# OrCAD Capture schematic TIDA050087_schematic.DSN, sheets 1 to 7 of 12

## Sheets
1 P07: i.MX93 MISC: size C
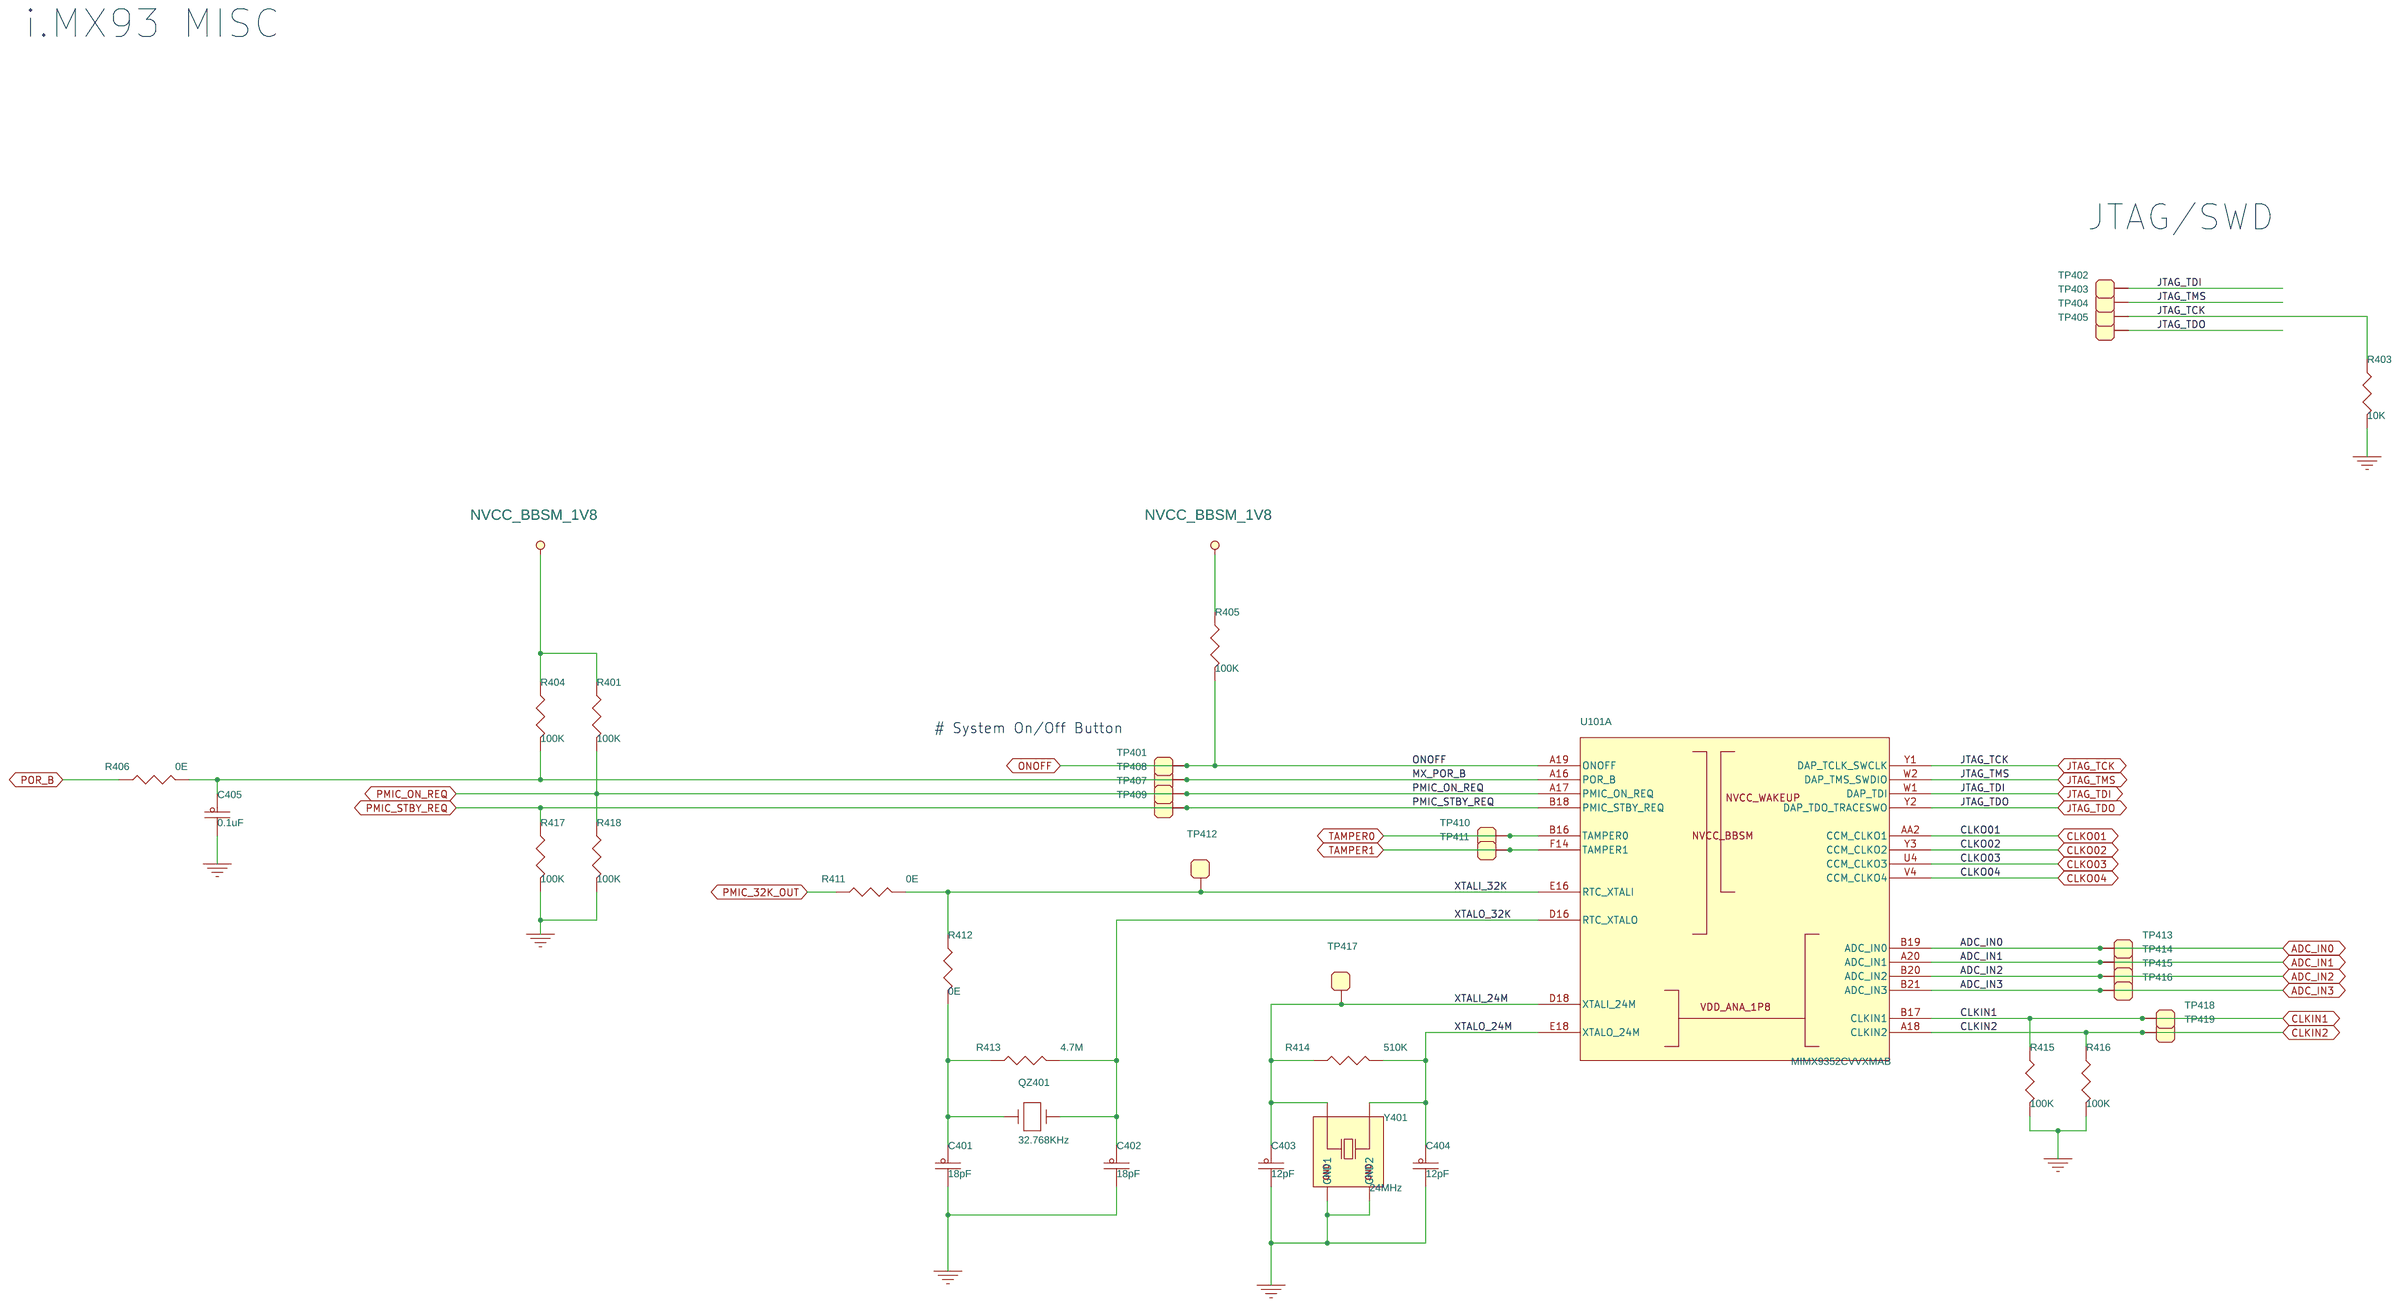
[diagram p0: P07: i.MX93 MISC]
2 P05: LPDDR4: size C
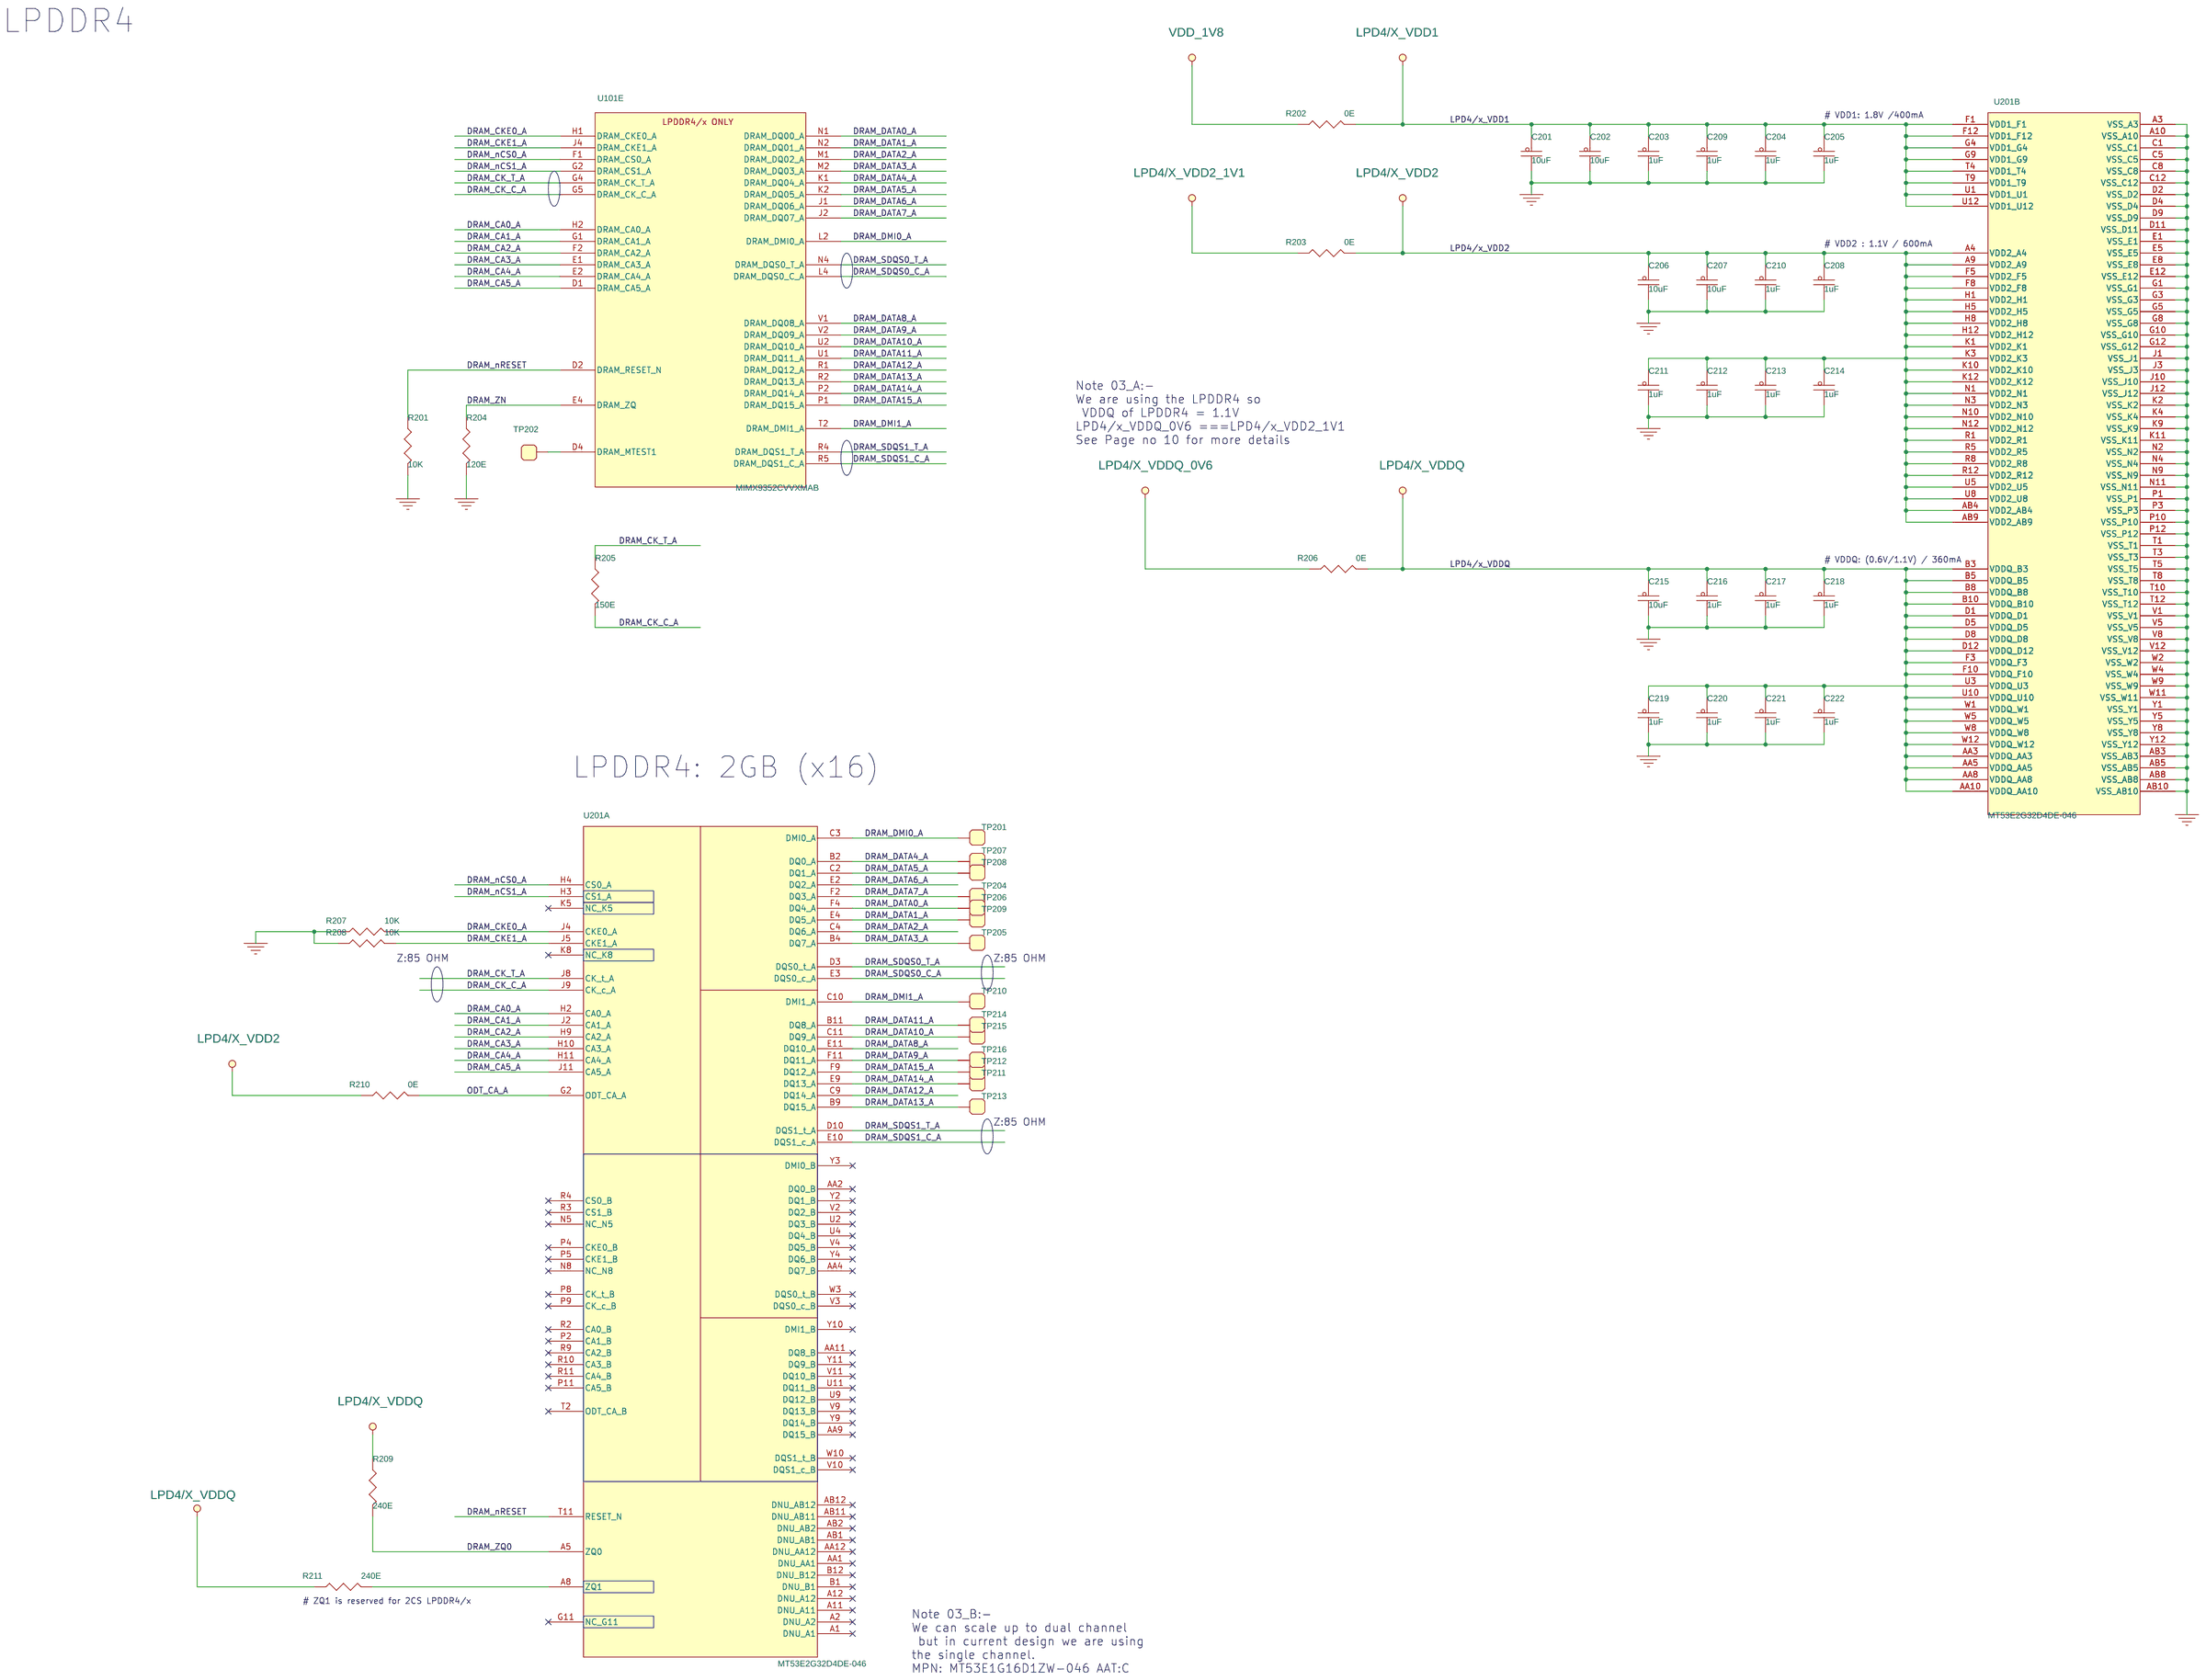
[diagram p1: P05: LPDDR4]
3 P08: eMMC: size C
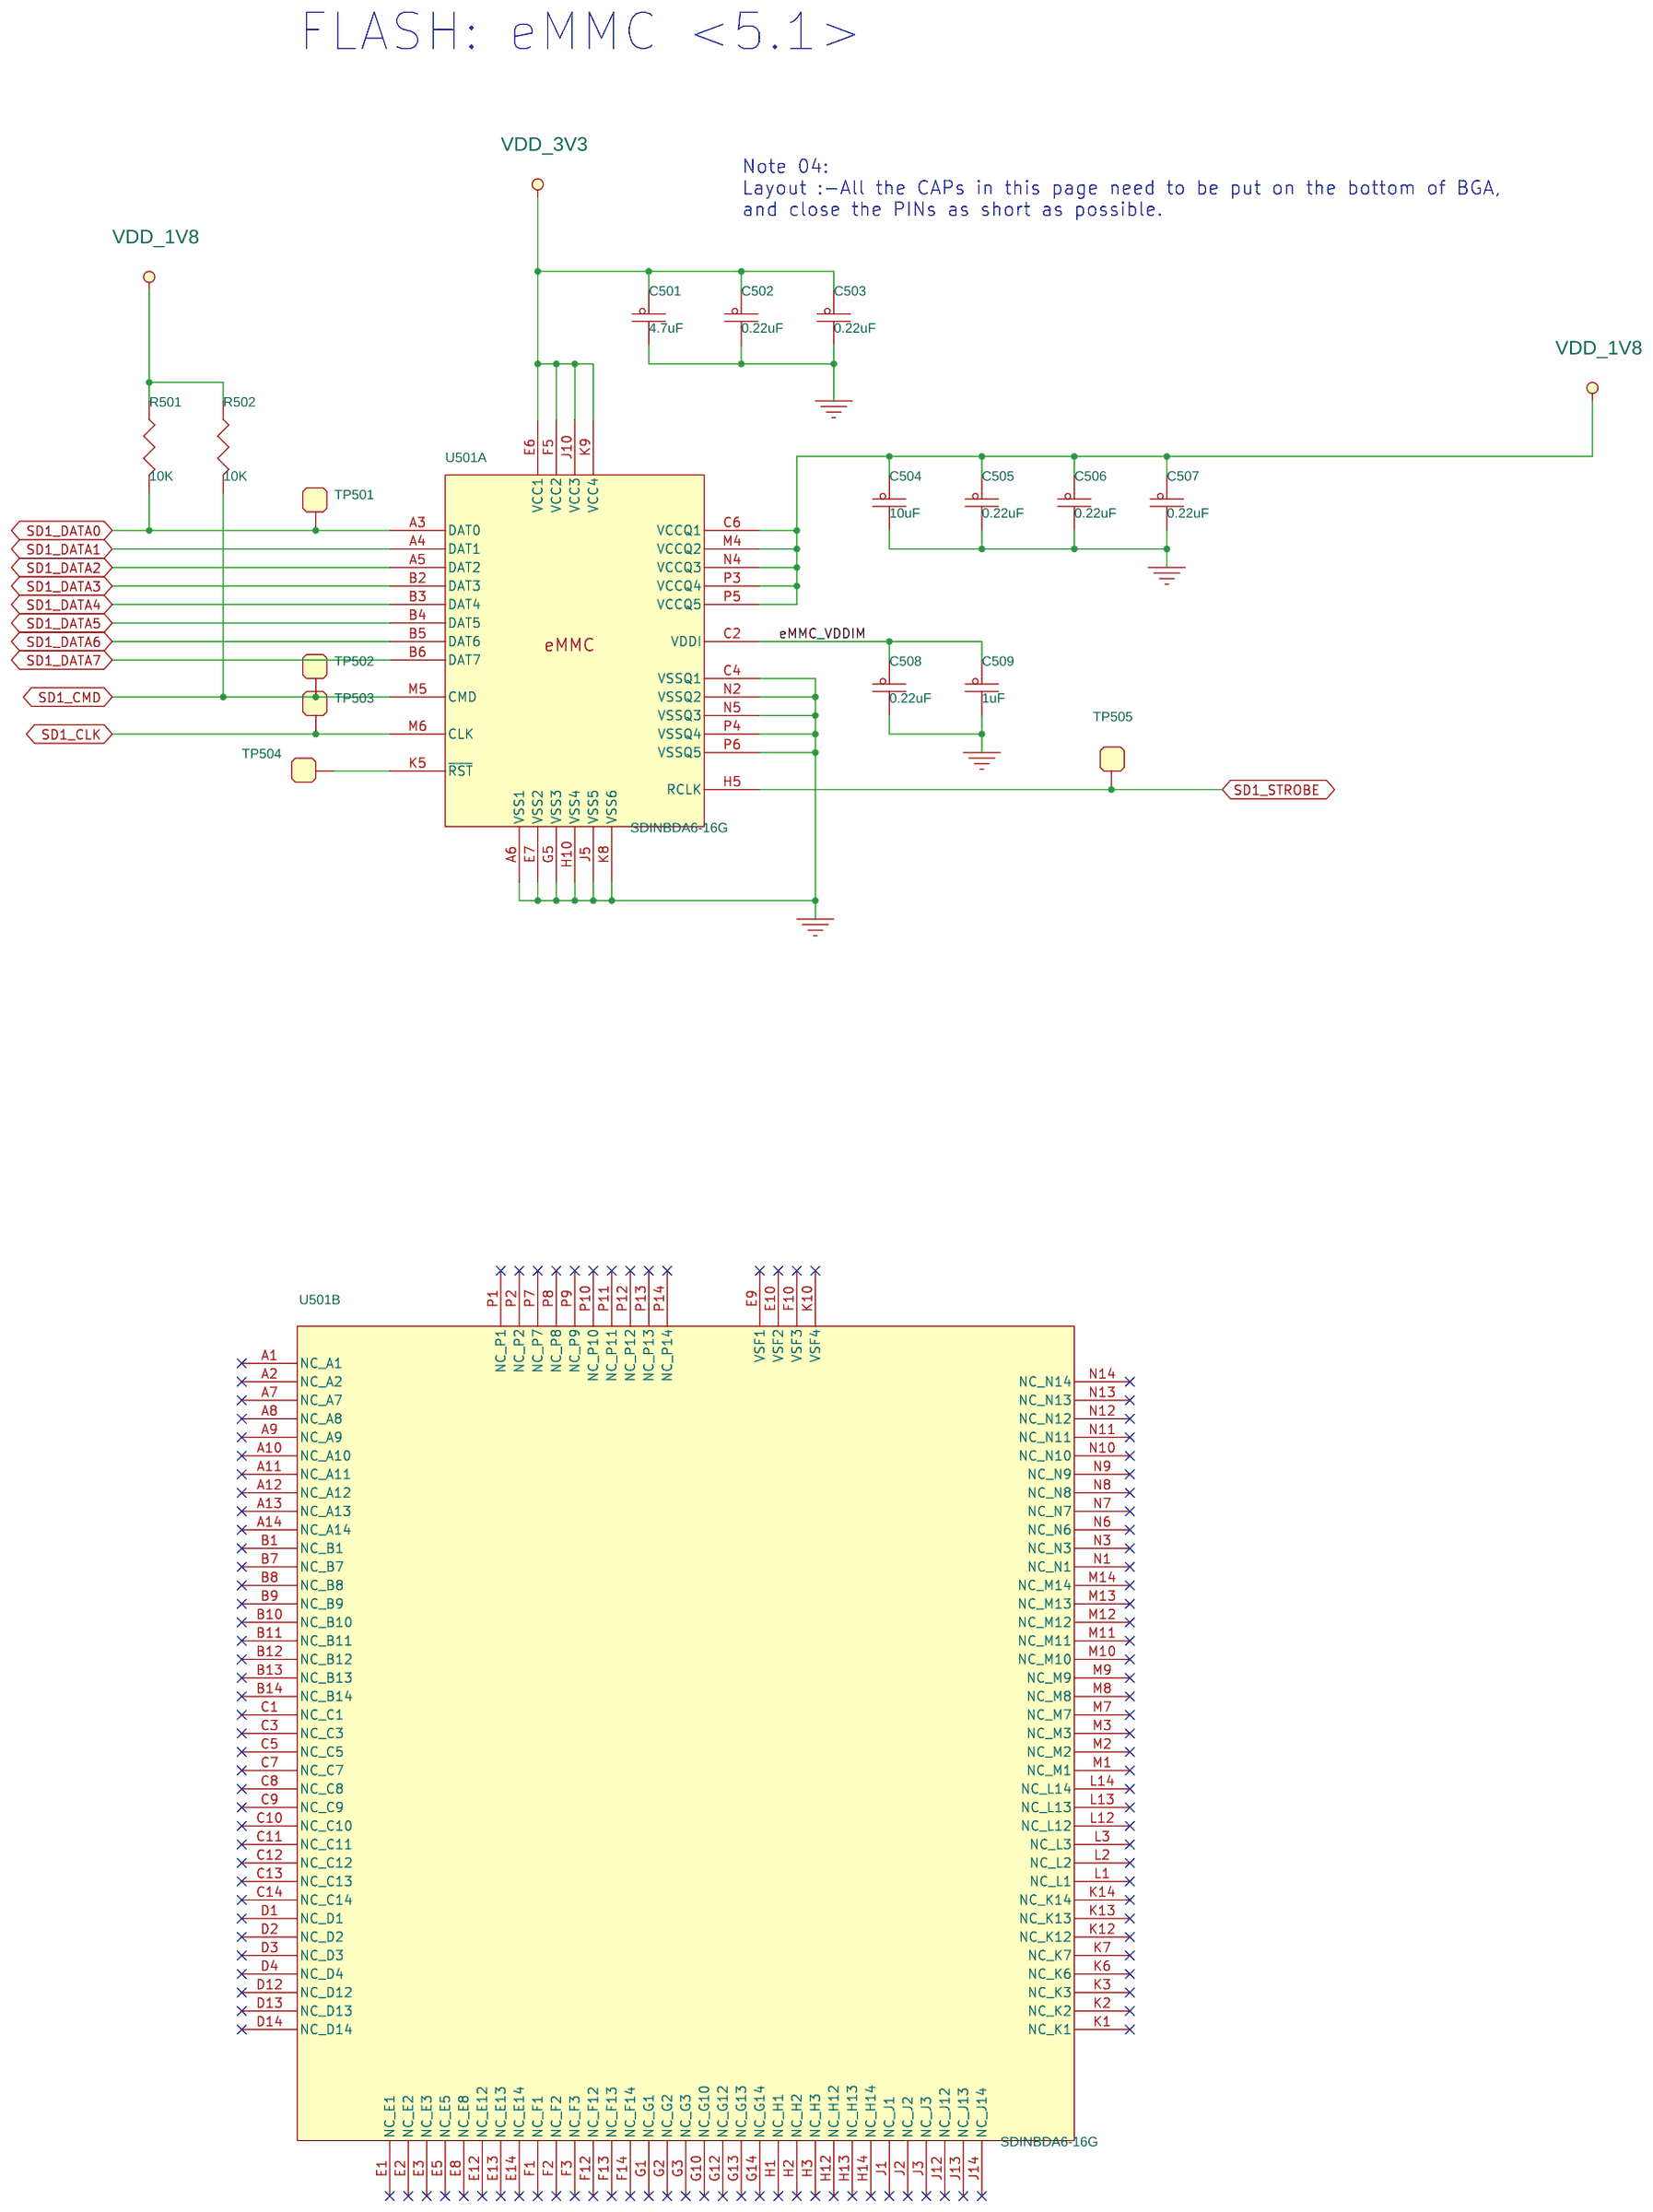
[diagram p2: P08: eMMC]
4 P01: COVER PAGE
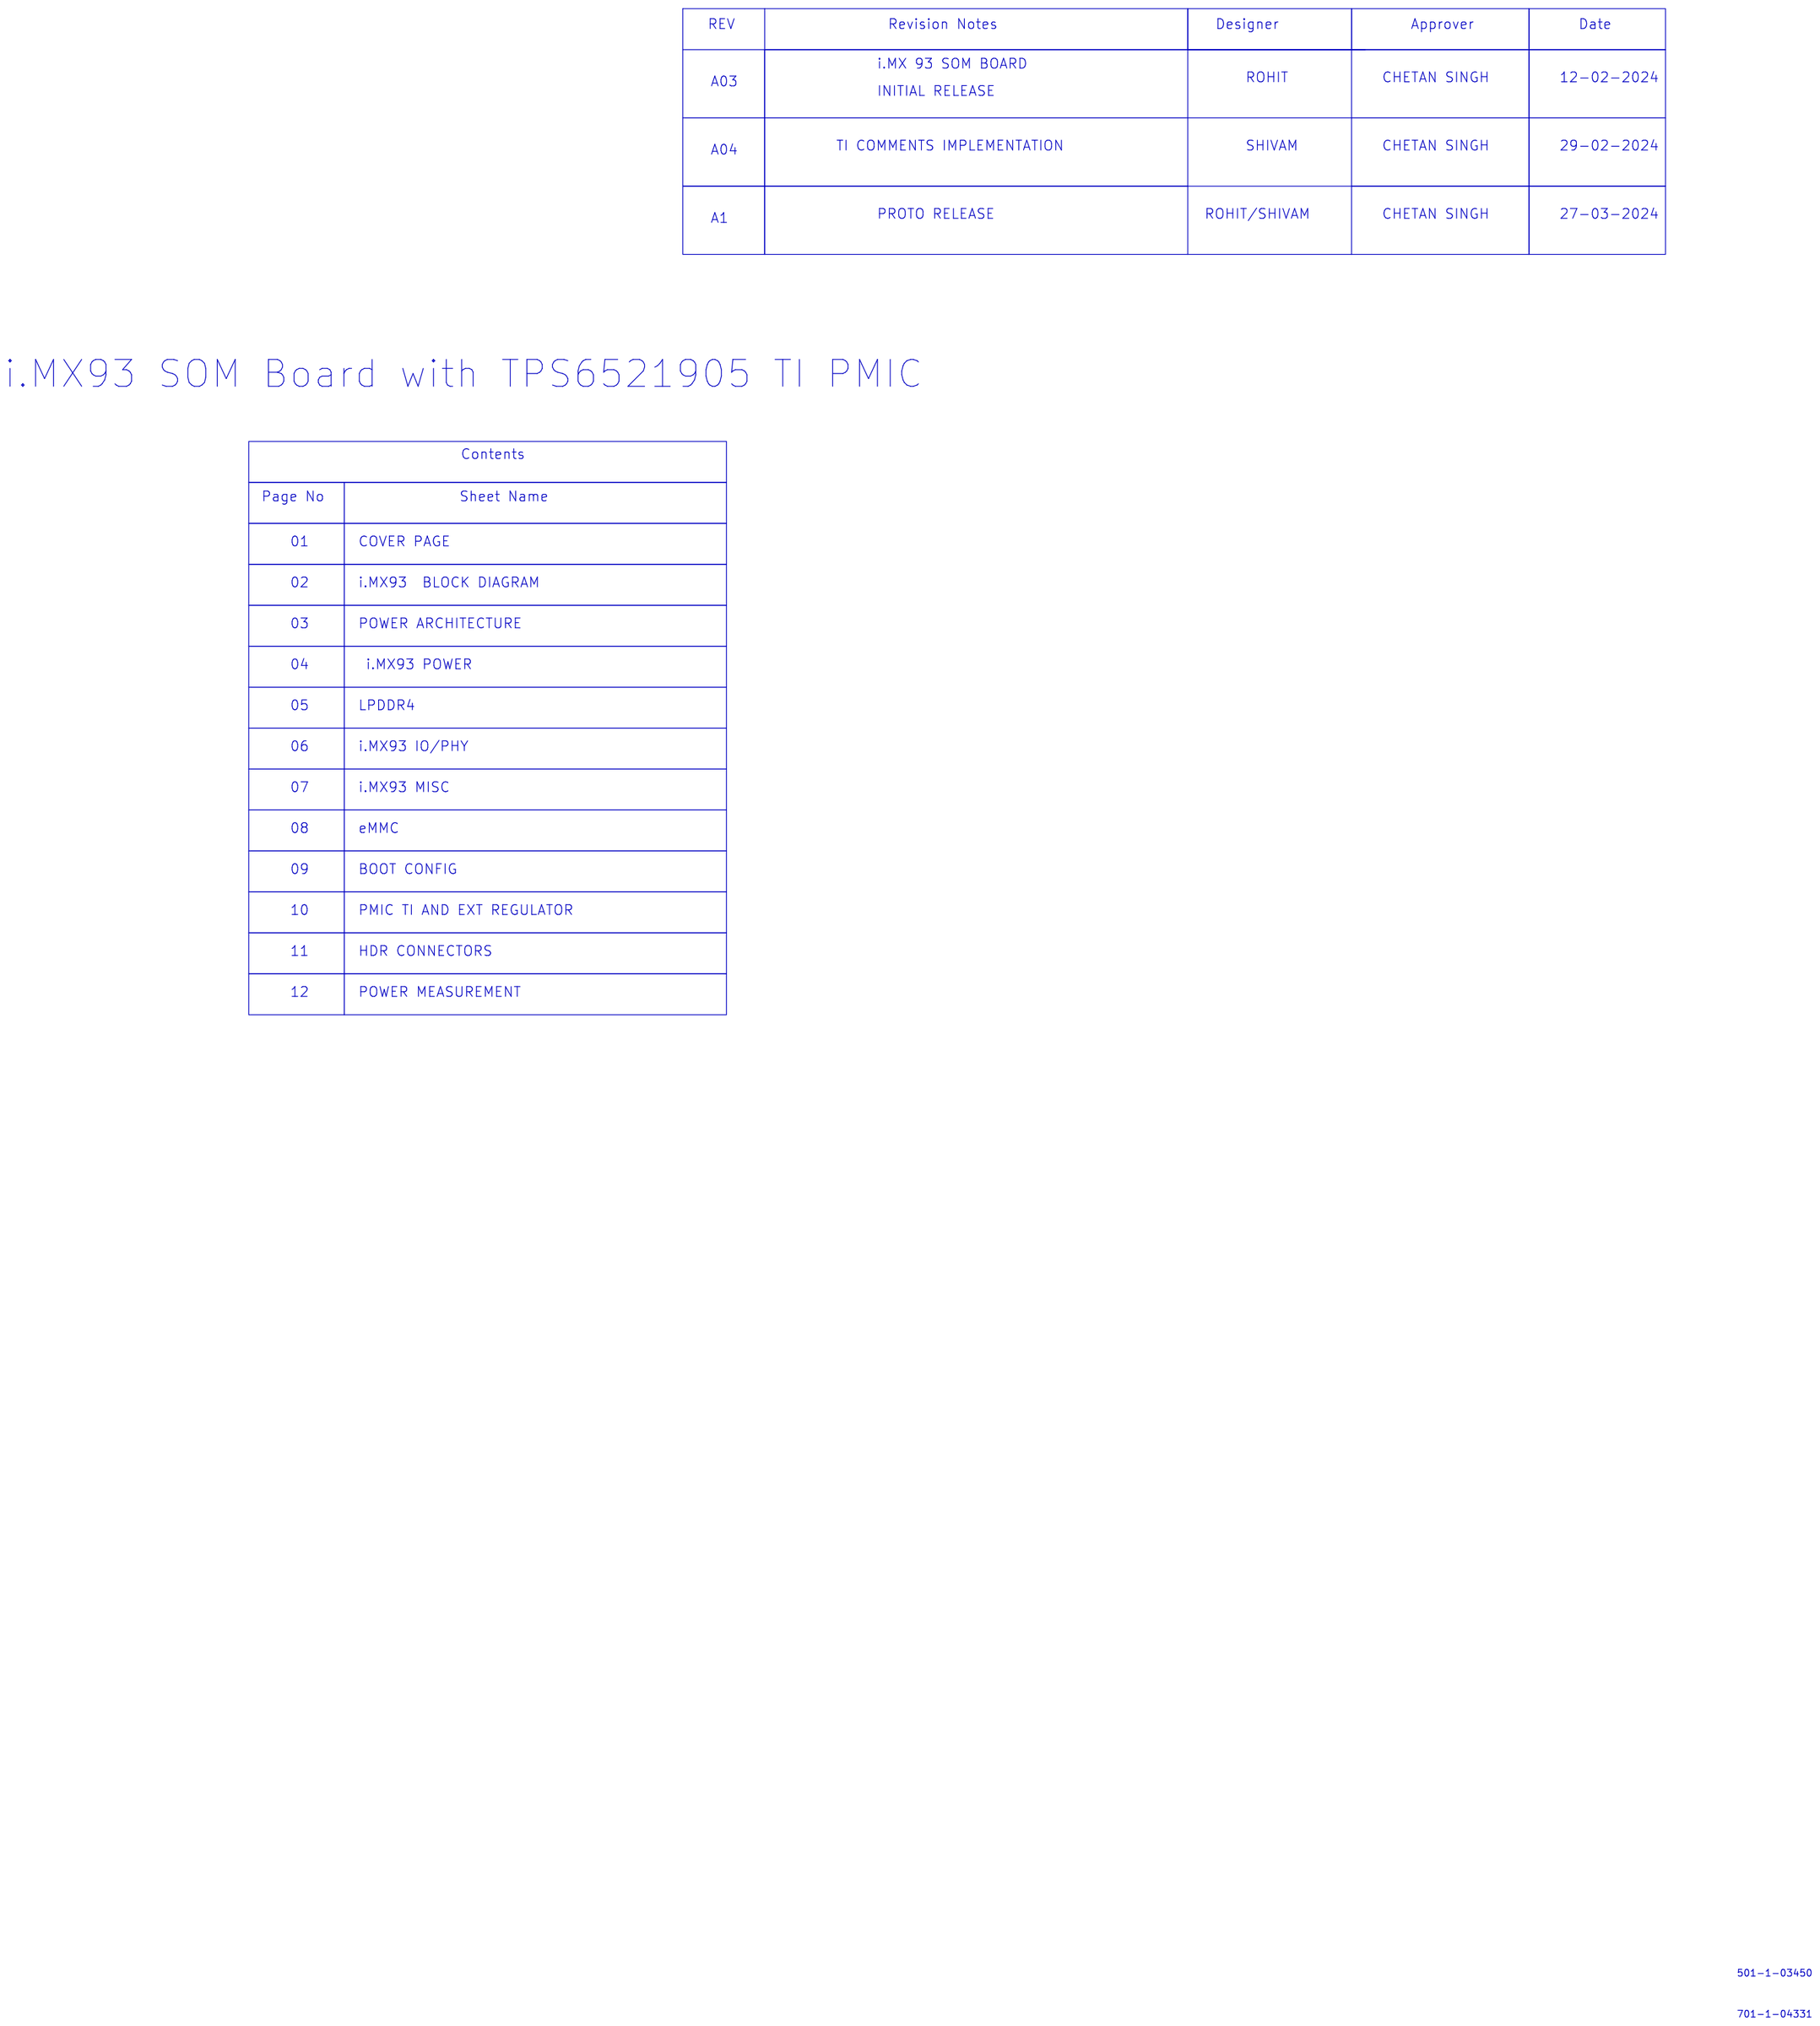
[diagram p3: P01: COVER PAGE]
5 P11: HDR CONNECTORS: size C
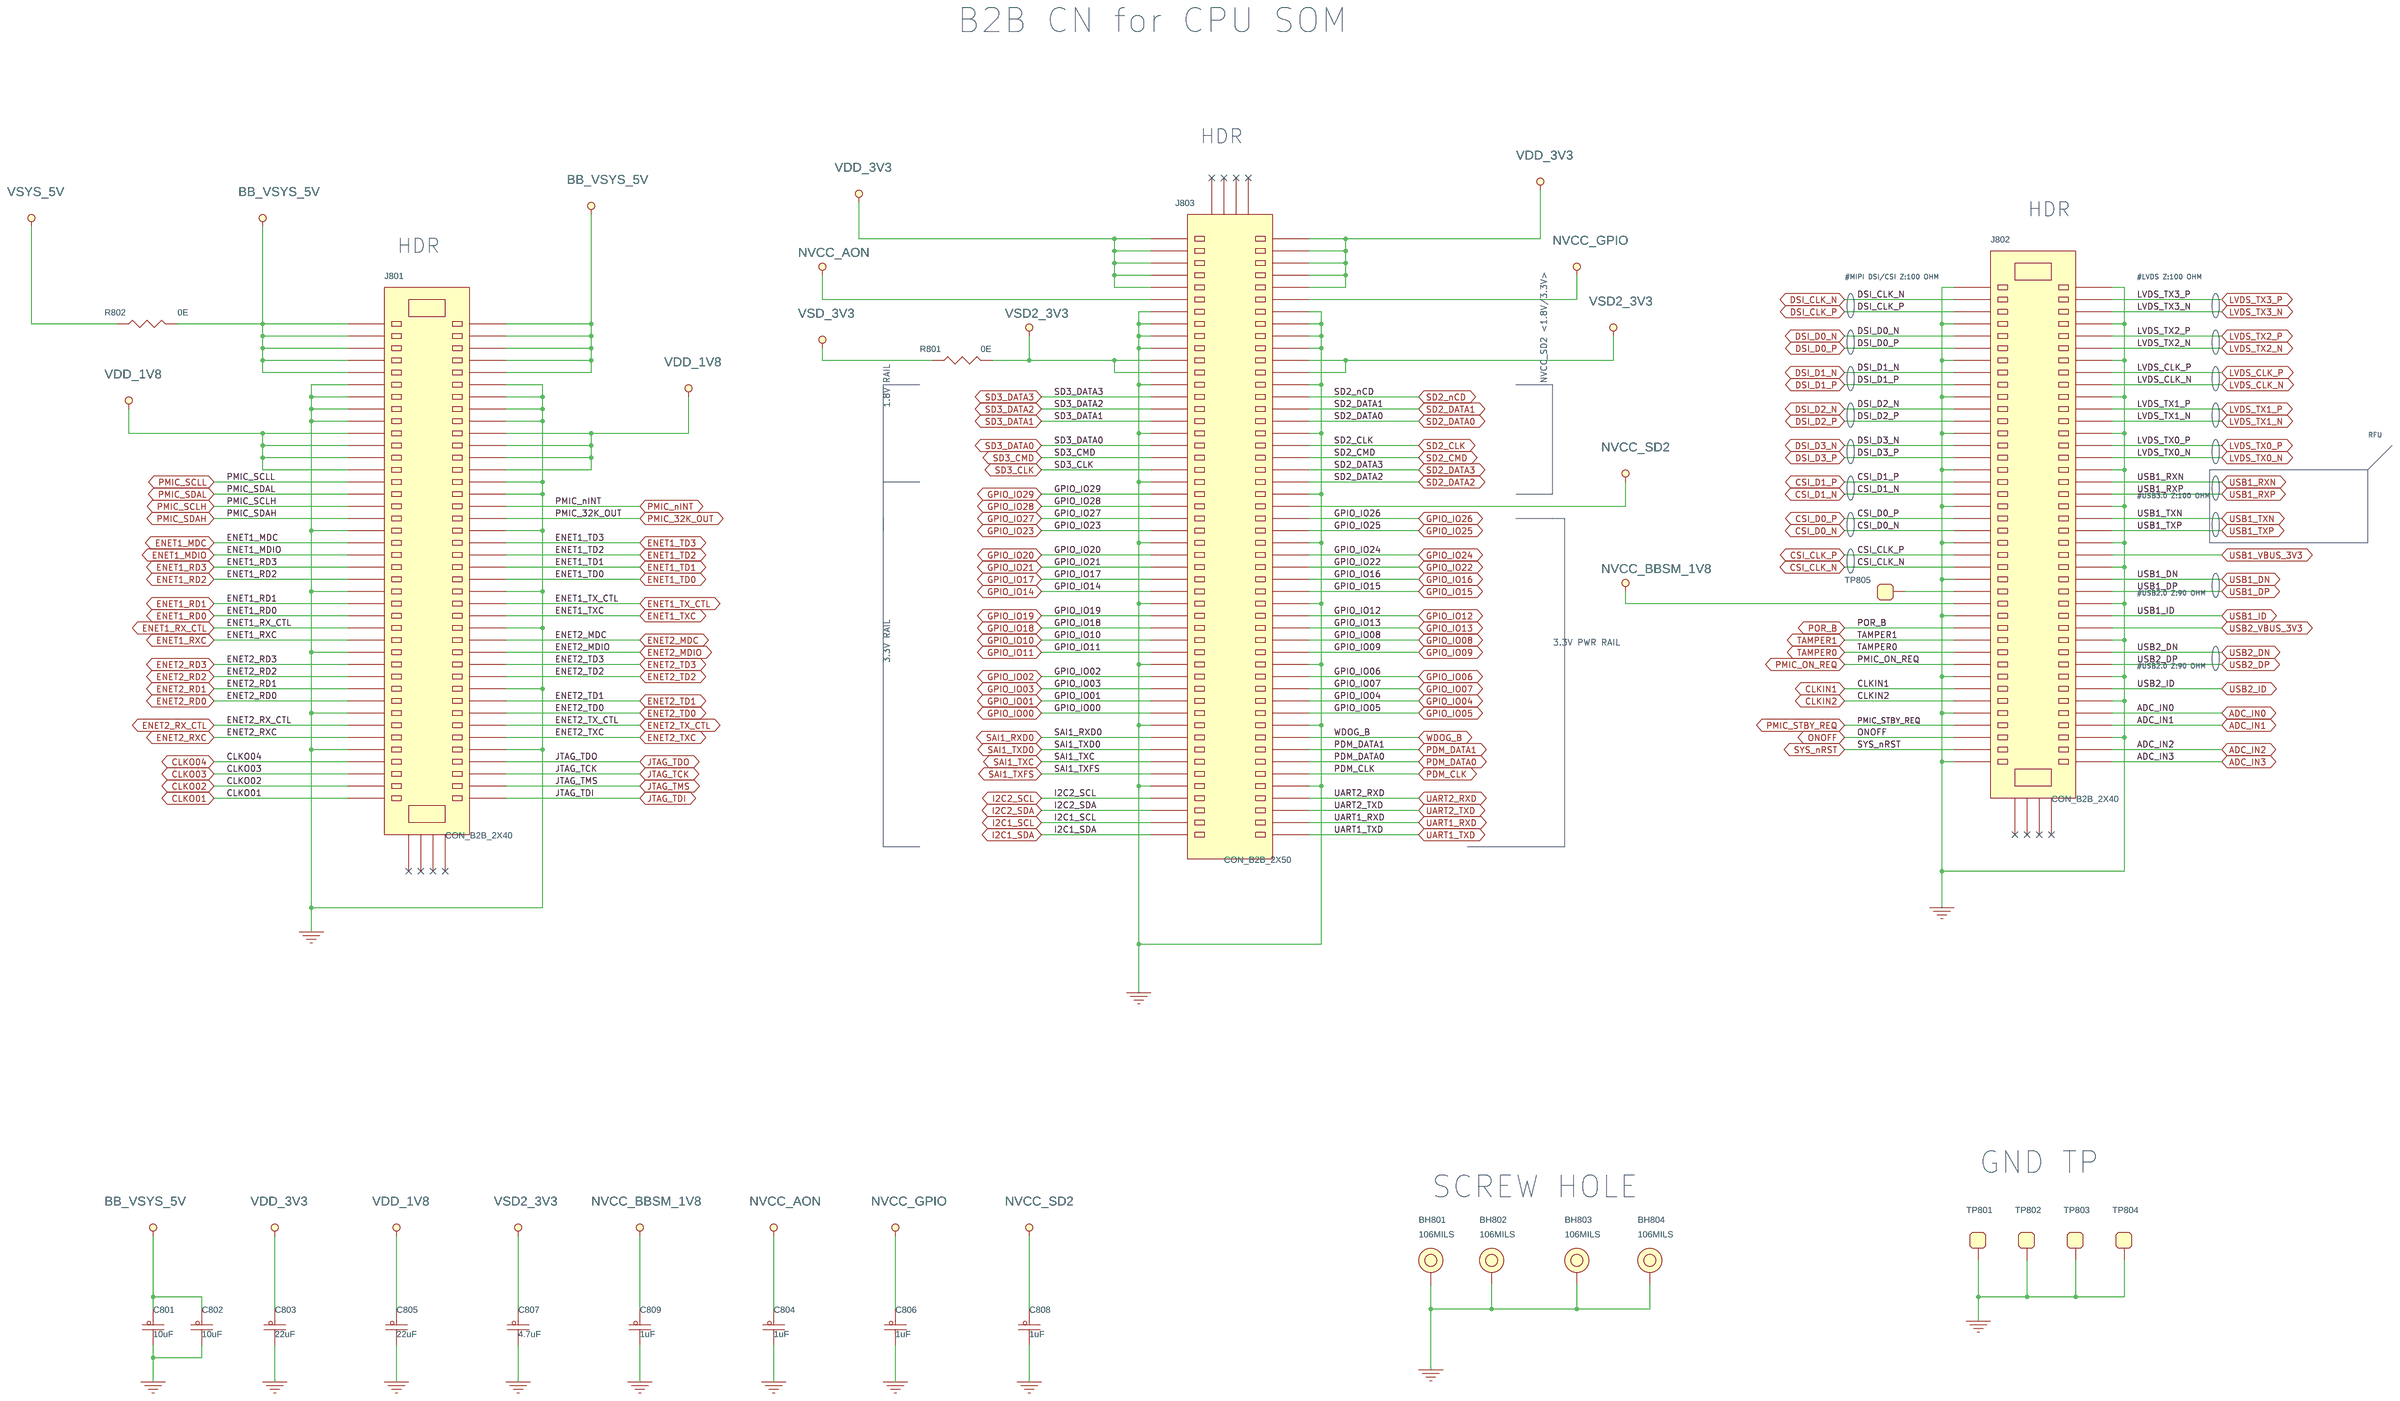
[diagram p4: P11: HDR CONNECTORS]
6 P04: i.MX93 POWER: size C
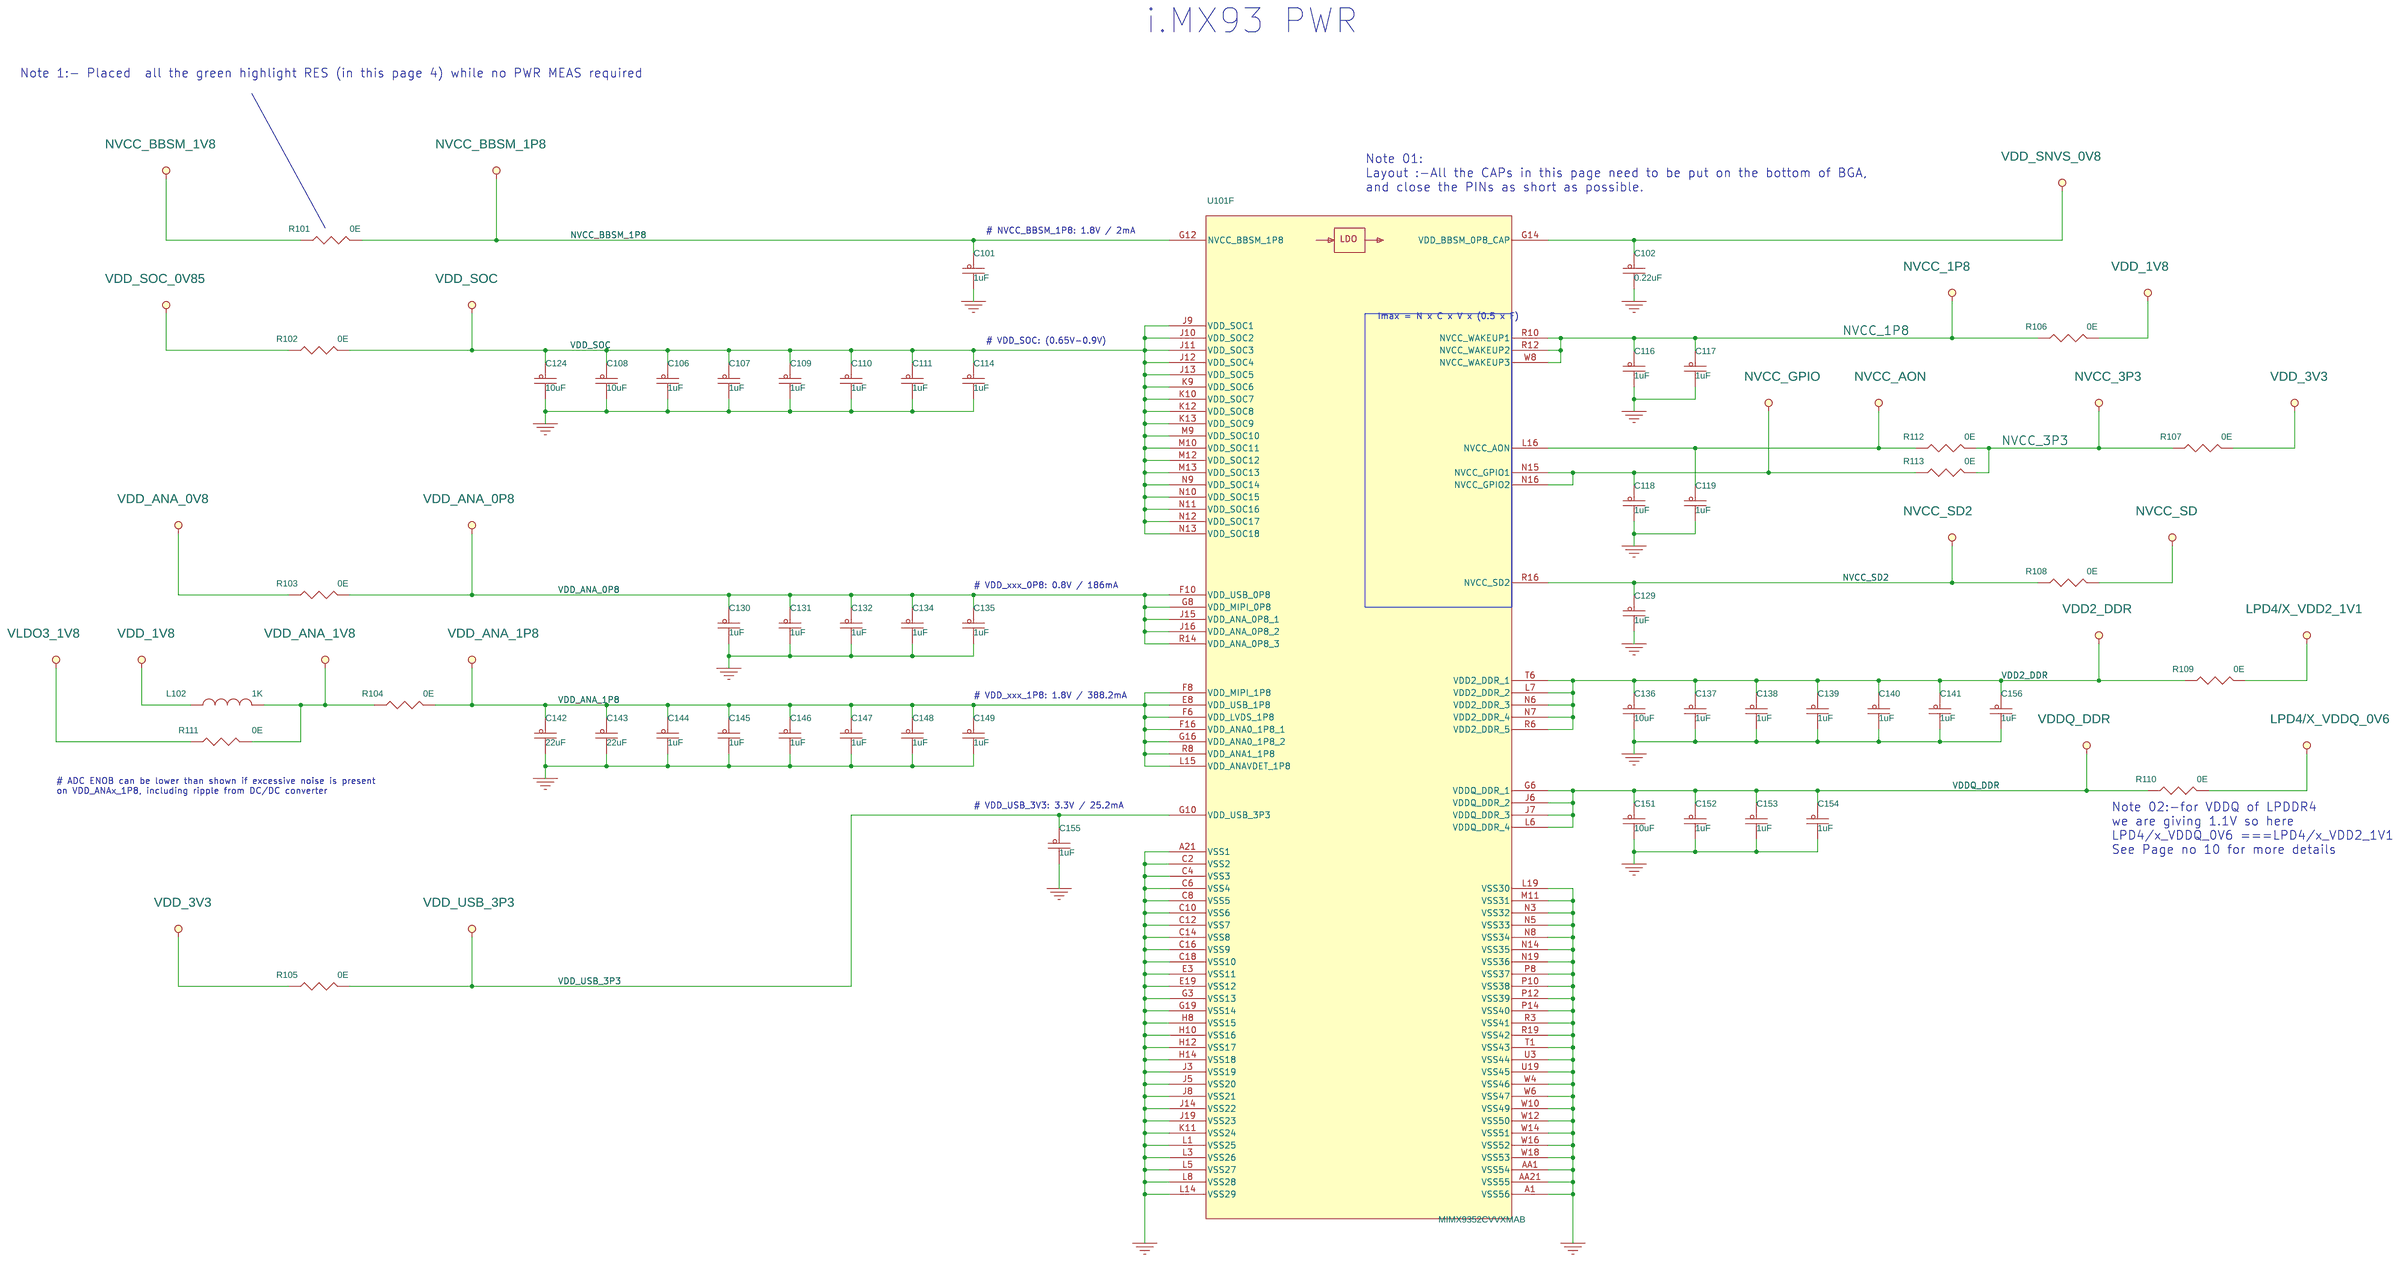
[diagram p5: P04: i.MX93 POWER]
7 P09: BOOT CONFIG: size C
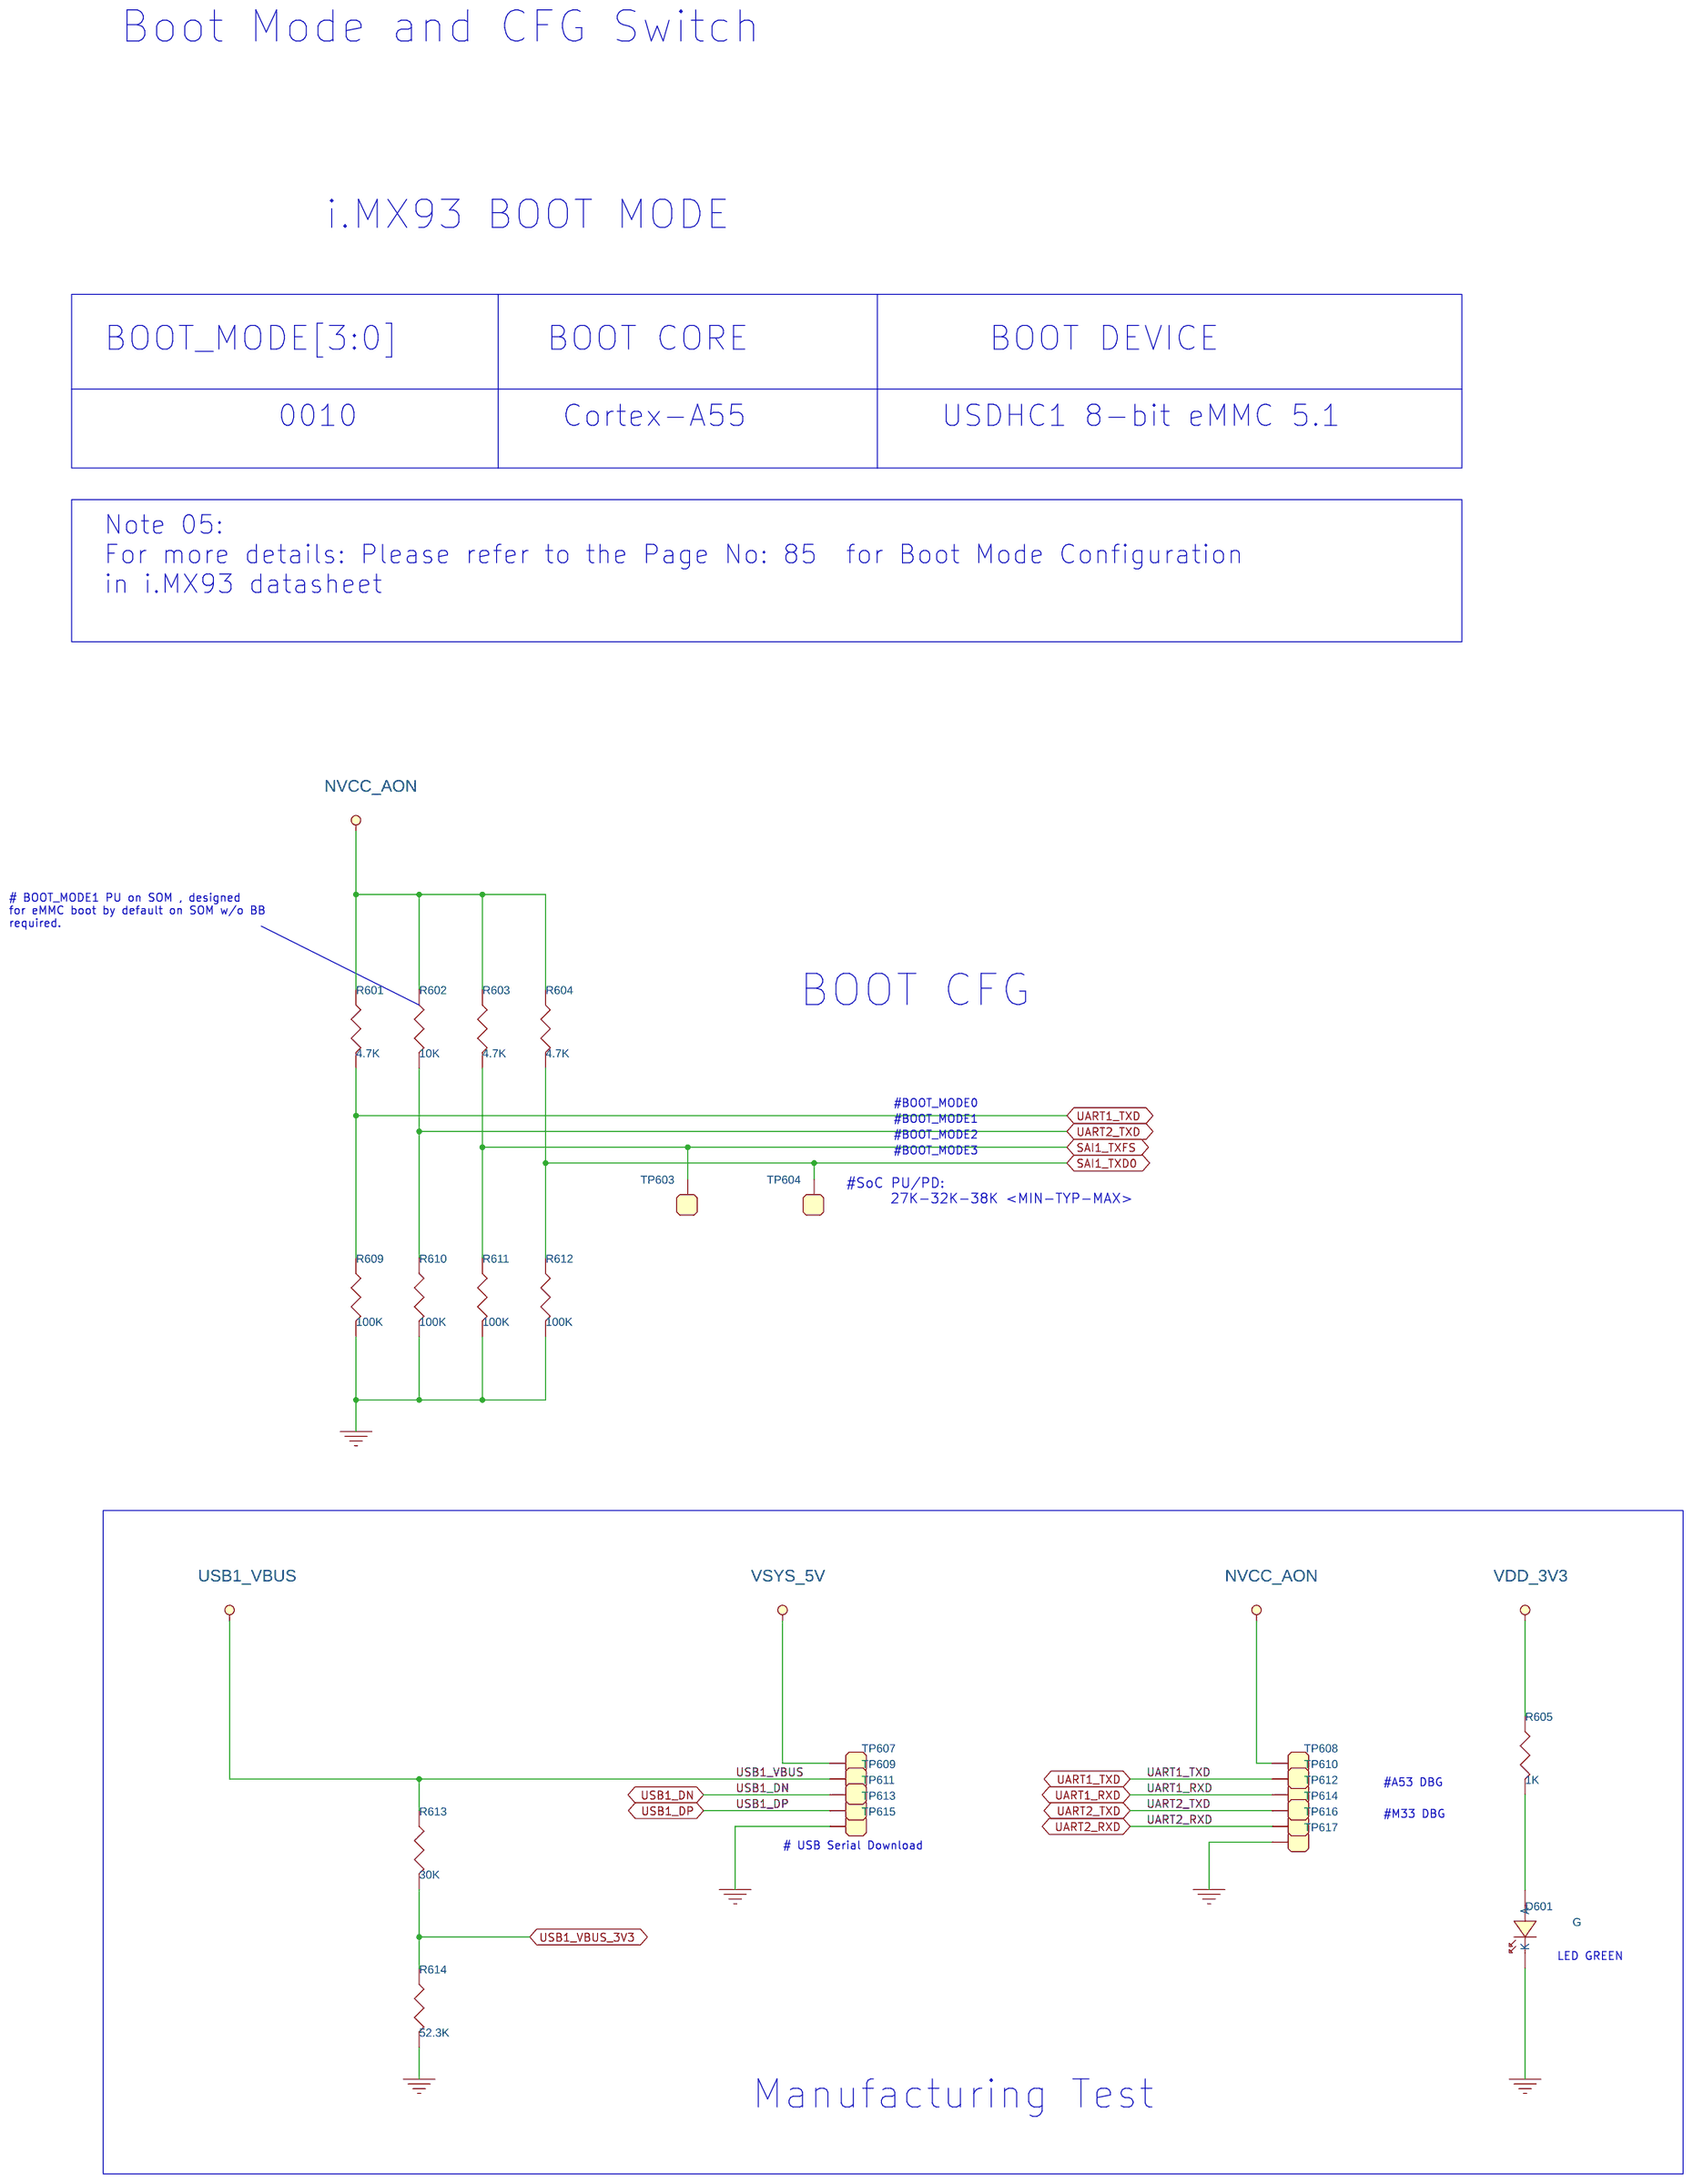
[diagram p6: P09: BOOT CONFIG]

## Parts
sheet P04: i.MX93 POWER
C101  1uF  [0201]
C102  0.22uF  [0201]
C106  1uF  [0201]
C107  1uF  [0201]
C108  10uF  [0402]
C109  1uF  [0201]
C110  1uF  [0201]
C111  1uF  [0201]
C114  1uF  [0201]
C116  1uF  [0201]
C117  1uF  [0201]
C118  1uF  [0201]
C119  1uF  [0201]
C124  10uF  [0402]
C129  1uF  [0201]
C130  1uF  [0201]
C131  1uF  [0201]
C132  1uF  [0201]
C134  1uF  [0201]
C135  1uF  [0201]
C136  10uF  [0402]
C137  1uF  [0201]
C138  1uF  [0201]
C139  1uF  [0201]
C140  1uF  [0201]
C141  1uF  [0201]
C142  22uF  [0603]
C143  22uF  [0603]
C144  1uF  [0201]
C145  1uF  [0201]
C146  1uF  [0201]
C147  1uF  [0201]
C148  1uF  [0201]
C149  1uF  [0201]
C151  10uF  [0402]
C152  1uF  [0201]
C153  1uF  [0201]
C154  1uF  [0201]
C155  1uF  [0201]
C156  1uF  [0201]
L102  1K  [FBEAD-0603_A_A1]
R101  0E  [0402]
R102  0E  [RC0805]
R103  0E  [RC0603]
R104  0E  [RC0603]
R105  0E  [0402]
R106  0E  [0402]
R107  0E  [0402]
R108  0E  [0402]
R109  0E  [RC0603]
R110  0E  [RC0603]
R111  0E  [RC0603]
R112  0E  [0402]
R113  0E  [0402]
sheet P05: LPDDR4
C201  10uF  [0402]
C202  10uF  [0402]
C203  1uF  [0201]
C204  1uF  [0201]
C205  1uF  [0201]
C206  10uF  [0402]
C207  10uF  [0402]
C208  1uF  [0201]
C209  1uF  [0201]
C210  1uF  [0201]
C211  1uF  [0201]
C212  1uF  [0201]
C213  1uF  [0201]
C214  1uF  [0201]
C215  10uF  [0402]
C216  1uF  [0201]
C217  1uF  [0201]
C218  1uF  [0201]
C219  1uF  [0201]
C220  1uF  [0201]
C221  1uF  [0201]
C222  1uF  [0201]
R201  10K  [0402]
R202  0E  [RC0603]
R203  0E  [RC0603]
R204  120E  [0402]
R205  150E  [0402]
R206  0E  [RC0603]
R207  10K  [0402]
R208  10K  [0402]
R209  240E  [0201]
R210  0E  [0402]
R211  240E  [0201]
TP201  SMD  [TP20_SMD]
TP202  SMD  [TP20_SMD]
TP204  SMD  [TP20_SMD]
TP205  SMD  [TP20_SMD]
TP206  SMD  [TP20_SMD]
TP207  SMD  [TP20_SMD]
TP208  SMD  [TP20_SMD]
TP209  SMD  [TP20_SMD]
TP210  SMD  [TP20_SMD]
TP211  SMD  [TP20_SMD]
TP212  SMD  [TP20_SMD]
TP213  SMD  [TP20_SMD]
TP214  SMD  [TP20_SMD]
TP215  SMD  [TP20_SMD]
TP216  SMD  [TP20_SMD]
U201  MT53E2G32D4DE-046  [BGA200_0P65_10X14P5_F_A1]  (sections A,B)
sheet P06: i.MX93 IO/PHY
U101  MIMX9352CVVXMAB  [BGA306_0P5_11X11_CST_A1]  (sections A,B,C,D,E,F)
sheet P07: i.MX93 MISC
C401  18pF  [0201]
C402  18pF  [0201]
C403  12pF  [0201]
C404  12pF  [0201]
C405  0.1uF  [0402]
QZ401  32.768KHz  [XTAL2_2P5_3P2X1P5]
R401  100K  [0402]
R403  10K  [0402]
R404  100K  [0402]
R405  100K  [0402]
R406  0E  [0201]
R411  0E  [0201]
R412  0E  [0201]
R413  4.7M  [0402]
R414  510K  [0402]
R415  100K  [0402]
R416  100K  [0402]
R417  100K  [0402]
R418  100K  [0402]
TP401  SMD  [TP20_SMD]
TP402  SMD  [TP20_SMD]
TP403  SMD  [TP20_SMD]
TP404  SMD  [TP20_SMD]
TP405  SMD  [TP20_SMD]
TP407  SMD  [TP20_SMD]
TP408  SMD  [TP20_SMD]
TP409  SMD  [TP20_SMD]
TP410  SMD  [TP20_SMD]
TP411  SMD  [TP20_SMD]
TP412  SMD  [TP20_SMD]
TP413  SMD  [TP20_SMD]
TP414  SMD  [TP20_SMD]
TP415  SMD  [TP20_SMD]
TP416  SMD  [TP20_SMD]
TP417  SMD  [TP20_SMD]
TP418  SMD  [TP20_SMD]
TP419  SMD  [TP20_SMD]
Y401  24MHz  [XTAL4_1P6_3P2X2P5_A_A1]
sheet P08: eMMC
C501  4.7uF  [0402]
C502  0.22uF  [0201]
C503  0.22uF  [0201]
C504  10uF  [0402]
C505  0.22uF  [0201]
C506  0.22uF  [0201]
C507  0.22uF  [0201]
C508  0.22uF  [0201]
C509  1uF  [0201]
R501  10K  [0402]
R502  10K  [0402]
TP501  SMD  [TP20_SMD]
TP502  SMD  [TP20_SMD]
TP503  SMD  [TP20_SMD]
TP504  SMD  [TP20_SMD]
TP505  SMD  [TP20_SMD]
U501  SDINBDA6-16G  [BGA153_0P5_11P5X13_C_A2]  (sections A,B)
sheet P09: BOOT CONFIG
D601  G  [LED-0603_L_A1]
R601  4.7K  [0402]
R602  10K  [0402]
R603  4.7K  [0402]
R604  4.7K  [0402]
R605  1K  [0402]
R609  100K  [0402]
R610  100K  [0402]
R611  100K  [0402]
R612  100K  [0402]
R613  30K  [0402]
R614  52.3K  [0201]
TP603  SMD  [TP35_SMD]
TP604  SMD  [TP35_SMD]
TP607  SMD  [TP35_SMD]
TP608  SMD  [TP35_SMD]
TP609  SMD  [TP35_SMD]
TP610  SMD  [TP35_SMD]
TP611  SMD  [TP35_SMD]
TP612  SMD  [TP35_SMD]
TP613  SMD  [TP35_SMD]
TP614  SMD  [TP35_SMD]
TP615  SMD  [TP35_SMD]
TP616  SMD  [TP35_SMD]
TP617  SMD  [TP35_SMD]
sheet P11: HDR CONNECTORS
BH801  106MILS  [MH_CIR173D106T_CUST]
BH802  106MILS  [MH_CIR173D106T_CUST]
BH803  106MILS  [MH_CIR173D106T_CUST]
BH804  106MILS  [MH_CIR173D106T_CUST]
C801  10uF  [0603]
C802  10uF  [0603]
C803  22uF  [0603]
C804  1uF  [0201]
C805  22uF  [0603]
C806  1uF  [0201]
C807  4.7uF  [0402]
C808  1uF  [0201]
C809  1uF  [0201]
J801  CON_B2B_2X40  [CON_B2B_2X40M_0P4_SM_ST_D_A1]
J802  CON_B2B_2X40  [CON_B2B_2X40M_0P4_SM_ST_D_A1]
J803  CON_B2B_2X50  [CON_B2B_2X50M_0P4_SM_ST_A_A2]
R801  0E  [RC0603]
R802  0E  [RC0805]
TP801  SMD  [TP50_SMD]
TP802  SMD  [TP50_SMD]
TP803  SMD  [TP50_SMD]
TP804  SMD  [TP50_SMD]
TP805  SMD  [TP35_SMD]

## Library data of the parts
C101 C106 C107 C109-C111 C114 C116-C119 C129-C132 C134 C135 C137-C141 C144-C149 C152-C156 C203-C205 C208-C214 C216-C222 C509 C804 C806 C808 C809 = CAP_NP: Cap, Cer-X5R, 1uF, 10V, 10%, 0201; EN: 102-1-02132; KEY Number: 102-1-02132@1; Mfg: SAMSUNG ELECTRO-MECHANICS AMERICA, INC; Mfg Part No: CL03A105KP3NSNC; Part Status: 3SILVER; RoHS Status: ROHS; Temperature: -55°C to +85°C
C102 C502 C503 C505-C508 = CAP_NP: Cap, Cer-X5R, 0.22uF, 10V, 20%, 0201; EN: 102-1-02582; KEY Number: 102-1-02582@1; Mfg: TAIYO YUDEN; Mfg Part No: LMK063BJ224MP-F; Part Status: 3SILVER; Temperature: -55°C to +85°C
C108 C124 C136 C151 C201 C202 C206 C207 C215 C504 = CAP_NP: Cap, Cer-X5R, 10uF, 6.3V, 20%, 0402; EN: 102-1-05247; KEY Number: 102-1-05247@1; Mfg: SAMSUNG ELECTRO-MECHANICS AMERICA, INC; Mfg Part No: CL05A106MQ5NUNC; Part Status: 3SILVER
C142 C143 C803 C805 = CAP_NP: Cap, Cer-X5R, 22uF, 10V, 20%, 0603; EN: 102-1-01791; KEY Number: 102-1-01791@1; Mfg: TDK CORPORATION; Mfg Part No: C1608X5R1A226M080AC; Part Status: 3SILVER; RoHS Status: RoHS; Temperature: -55°C to +85°C
L102 = FER_BEAD: F-Bead, 1K, 1.2A, SMD0603; EN: 104-1-00485; KEY Number: 104-1-00485@1; Mfg: MURATA MANUFACTURING CO,LTD; Mfg Part No: BLM18SP102SN1D; Part Status: 3SILVER; RoHS Status: RoHS; Temperature: -55°C to +125°C
R101 R105-R108 R112 R113 R210 = RES: Res, Chip, 0E, 1/16W, 5%, 0402; EN: 101-1-08134; KEY Number: 101-1-08134@1; Mfg: YAGEO CORPORATION; Mfg Part No: RC0402JR-070RL; Part Status: 3SILVER; RoHS Status: RoHS; Temperature: -55°C to +155°C
R102 R802 = RES: Res, Chip, 0E, 1/8W, 5A, 0805; EN: 101-1-03831; KEY Number: 101-1-03831@1; Mfg: YAGEO CORPORATION; Mfg Part No: RC0805JR-070RL; Part Status: 3SILVER; Temperature: -55°C to +155°C
R103 R104 R109-R111 R202 R203 R206 R801 = RES: Res, Chip, 0E, 1/10W, 1A, 0603; EN: 101-1-08684; KEY Number: 101-1-08684@1; Mfg: WALSIN TECHNOLOGY CORP.; Mfg Part No: WR06X000 PTL; Part Status: 3SILVER; RoHS Status: RoHS; Temperature: -55°C to +155°C
R201 R207 R208 R403 R501 R502 R602 = RES: Res, Chip, 10K, 1/16W, 5%, AEC-Q200, 0402; EN: 101-1-04836; KEY Number: 101-1-04836@1; Mfg: VISHAY INTERTECHNOLOGY, INC; Mfg Part No: CRCW040210K0JNED; Part Status: 3SILVER; Temperature: -55°C to +155°C
R204 = RES: Res, Chip, 120E, 1/10W, 1%, AEC-Q200, 0402; EN: 101-1-03878; KEY Number: 101-1-03878@1; Mfg: PANASONIC INDUSTRY CO., LTD; Mfg Part No: ERJ2RKF1200X; Part Status: 3SILVER; Temperature: -55°C to +155°C
R205 = RES: Res, Chip, 150E, 1/16W, 1%, 0402; EN: 101-1-08696; KEY Number: 101-1-08696@1; Mfg: NIC COMPONENTS; Mfg Part No: NRCL04F1500TRF; Part Status: 3SILVER; RoHS Status: RoHS, Pb Free; Temperature: -55°C to +155°C
R209 R211 = RES: Res, Chip, 240E, 1/20W, 1%, 0201; EN: 101-1-03558; KEY Number: 101-1-03558@1; Mfg: YAGEO CORPORATION; Mfg Part No: RC0201FR-07240RL; Part Status: 4GOLD; RoHS Status: RoHS, HalogenFree; Temperature: -55°C to +155°C
TP201 TP202 TP204-TP216 TP401-TP405 TP407-TP419 TP501-TP505 = TEST_POINT_SMD: Testpoint, Pad=0.5mm, SM=0.65mm, SMD; EN: 666-1-00037; KEY Number: 666-1-00037@1; Mfg: NA; Mfg Part No: 666-1-00037; Part Status: 3SILVER; Temperature: NA
U201 = CST_IC_DDR4-SDRAMX32_200P_A1: IC, LPDDR4 SDRAM, 8GB, x32bit, 2133MHz, AEC-Q100, TFBGA-200; EN: 301-2-01536; KEY Number: 301-2-01536@1; Mfg: MICRON TECHNOLOGY, INC.; Mfg Part No: MT53E2G32D4DE-046 AAT:C; Part Status: 3SILVER; RoHS Status: RoHS, Green; Temperature: -40°C to +105°C
U101 = CST_IC_MIMX93XX_BGA-306P_A1: IC, SoC, i.MX93, ARM Cortex-A55 Dual Core, 1.7GHz, FCBGA-306; EN: 301-1-01081; KEY Number: 301-1-01081@1; Mfg: NXP SEMICONDUCTORS; Part Status: 3SILVER; RoHS Status: RoHS; Temperature: -40°C to +105°C
C401 C402 = CAP_NP: Cap, Cer-NPO, 18pF, 50V, 5%, 0201; EN: 102-1-01943; KEY Number: 102-1-01943@3; Mfg: MURATA MANUFACTURING CO,LTD; Mfg Part No: GRM0335C1H180JA01D; Part Status: 3SILVER; Temperature: -55°C to +125°C
C403 C404 = CAP_NP: Cap, Cer-NPO, 12pF, 25V, 5%, AEC-Q200, 0201; EN: 102-1-05197; KEY Number: 102-1-05197@1; Mfg: TDK CORPORATION; Mfg Part No: CGA1A2C0G1E120J030BA; Part Status: 3SILVER; RoHS Status: RoHS; Temperature: -55°C to +125°C
C405 = CAP_NP: Cap, Cer-X5R, 0.1uF, 25V, 10%, 0402; EN: 102-1-07356; KEY Number: 102-1-07356@5; Mfg: YAGEO CORPORATION; Mfg Part No: CC0402KRX5R8BB104; Part Status: 3SILVER
QZ401 = CRYSTAL: XTAL, 32.768KHz, 12.5pF, +/-20ppm, 70K, 3.2x1.5mm, SMD; EN: 108-1-00009; KEY Number: 108-1-00009@4; Mfg: ABRACON CORPORATION; Mfg Part No: ABS07-32.768KHZ-T; Part Status: 3SILVER; RoHS Status: ROHS; Temperature: -40°C to +85°C
R401 R404 R405 R415-R418 R609-R612 = RES: Res, Chip, 100K, 1/16W, 5%, 0402; EN: 101-1-11924; KEY Number: 101-1-11924@1; Mfg: VENKEL CORP; Mfg Part No: CR0402-16W-104JT
R406 R411 R412 = RES: Res, Chip, 0E, 1/20W, 1A, 0201; EN: 101-1-12661; KEY Number: 101-1-12661@1; Mfg: BOURNS INC; Mfg Part No: CR0201-J/-000GLF
R413 = RES: Res, Chip, 4.7M, 1/16W, 1%, 0402; EN: 101-1-08698; KEY Number: 101-1-08698@1; Mfg: YAGEO CORPORATION; Mfg Part No: RC0402FR-074M7L; Part Status: 3SILVER; RoHS Status: RoHS, Halogen Free; Temperature: -55°C to +155°C
R414 = RES: Res, Chip, 510K, 1/10W, 5%, AEC-Q200, 0402; EN: 101-1-08702; KEY Number: 101-1-08702@1; Mfg: PANASONIC INDUSTRY CO., LTD; Mfg Part No: ERJ2GEJ514X; Part Status: 3SILVER; RoHS Status: RoHS; Temperature: -55°C to +155°C
Y401 = CRYSTAL_4P: XTAL, 24MHz, 9pF, +/-10ppm, 40E, 3.2x2.5mm, SMD; EN: 108-1-00843; KEY Number: 108-1-00843@1; Mfg: SEIKO EPSON CORPORATION; Mfg Part No: TSX-3225 24.0000MF15X-AC3; Part Status: 2CUSTOM; RoHS Status: RoHS; Temperature: -40°C to +85°C
C501 C807 = CAP_NP: Cap, Cer-X5R, 4.7uF, 10V, 10%, 0402; EN: 102-1-07671; KEY Number: 102-1-07671@4; Mfg: SAMSUNG ELECTRO-MECHANICS AMERICA, INC; Mfg Part No: CL05A475KP5NRNC; Part Status: 3SILVER
U501 = CST_IC_NANDFLASH_BGA-153P_A1: IC, eMMC 5.1, 16GB, x1/x4/x8bit, 200MHz, TFBGA-153; EN: 301-2-01130; KEY Number: 301-2-01130@1; Mfg: WESTERN DIGITAL TECHNOLOGIES, INC.; Mfg Part No: SDINBDA6-16G-I1; Part Status: 2CUSTOM; RoHS Status: RoHS; Temperature: -25°C to +85°C
D601 = DIODE_LED: LED, Single, Green, 2.1V, 30mA, 140deg, 566nm, 28mcd, 0603; EN: 106-4-00005; KEY Number: 106-4-00005@1; Mfg: DIALIGHT; Mfg Part No: 598-8070-107F; Part Status: 3SILVER; RoHS Status: RoHS; Temperature: -40°C to +100°C
R601 R603 R604 = RES: Res, Chip, 4.7K, 1/10W, 5%, AEC-Q200, 0402; EN: 101-1-02785; KEY Number: 101-1-02785@1; Mfg: KOA SPEER ELECTRONICS, INC; Mfg Part No: RK73B1ETTP472J; Part Status: 3SILVER; RoHS Status: RoHS; Temperature: -55°C to +155°C
R605 = RES: Res, Chip, 1K, 1/16W, 1%, 0402; EN: 101-1-12620; KEY Number: 101-1-12620@1; Mfg: YAGEO CORPORATION; Mfg Part No: RC0402FR-071KL
R613 = RES: Res, Chip, 30K, 1/10W, 1%, AEC-Q200, 0402; EN: 101-1-13529; KEY Number: 101-1-13529@1; Mfg: KOA SPEER ELECTRONICS, INC; Mfg Part No: RK73H1ETTP3002F
R614 = RES: Res, Chip, 52.3K, 1/20W, 1%, 0201; EN: 101-1-07607; KEY Number: 101-1-07607@1; Mfg: YAGEO CORPORATION; Mfg Part No: RC0201FR-0752K3L; Part Status: 3SILVER; RoHS Status: RoHS; Temperature: -55°C to +125°C
TP603 TP604 TP607-TP617 TP805 = TEST_POINT_SMD: Testpoint, Pad=0.89mm, SM=0.99mm, SMD; EN: 666-1-00039; KEY Number: 666-1-00039@1; Mfg: NA; Mfg Part No: 666-1-00039; Part Status: 3SILVER
BH801-BH804 = MECH_MH_PL: MH, PTH, Pad=4.4mm, Via=2.7mm; EN: 666-1-00742; KEY Number: 666-1-00742@1; Mfg: NA; Mfg Part No: 666-1-00742; Part Status: 3SILVER; RoHS Status: NA; Temperature: NA
C801 C802 = CAP_NP: Cap, Cer-X5R, 10uF, 16V, 10%, 0603; EN: 102-1-02754; KEY Number: 102-1-02754@1; Mfg: MURATA MANUFACTURING CO,LTD; Mfg Part No: GRM188R61C106KAALD; Part Status: 3SILVER; RoHS Status: ROHS; Temperature: -55°C to +85°C
J801 J802 = CONN_B2B_2X40_84P_A_A1: Conn, B2B, Plug, 2x40, 0.4mm, 0.3A, Shrouded, ST, SMD; EN: 201-1-01193; KEY Number: 201-1-01193@1; Mfg: HRS (HIROSE ELECTRIC CO LTD); Mfg Part No: DF40C-80DP-0.4V(51); Part Status: 2CUSTOM; RoHS Status: RoHS; Temperature: -35°C to +85°C
J803 = CONN_B2B_2X50_104P: Conn, B2B, Plug, 2x50, 0.4mm, 0.3A, Shrouded, ST, SMD; EN: 201-1-01655; FPLIST: CON_B2B_2X50M_0P4_SM_ST_A_A1,CON_B2B_2X50M_0P4_SM_ST_CST_A1; KEY Number: 201-1-01655@1; Mfg: HRS (HIROSE ELECTRIC CO LTD); Mfg Part No: DF40C-100DP-0.4V(51); Part Status: 3SILVER; Temperature: -35°C to +85°C
TP801-TP804 = TEST_POINT_SMD: Testpoint, Pad=1.27mm, SM=1.37mm, SMD; EN: 666-1-00075; KEY Number: 666-1-00075@1; Mfg: NA; Mfg Part No: 666-1-00075; Part Status: 3SILVER

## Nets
GND: BH801.1 BH802.1 BH803.1 BH804.1 C101.2 C102.2 C106.2 C107.2 C108.2 C109.2 C110.2 C111.2 C114.2 C116.2 C117.2 C118.2 C119.2 C124.2 C129.2 C130.2 C131.2 C132.2 C134.2 C135.2 C136.2 C137.2 C138.2 C139.2 C140.2 C141.2 C142.2 C143.2 C144.2 C145.2 C146.2 C147.2 C148.2 C149.2 C151.2 C152.2 C153.2 C154.2 C155.2 C156.2 C201.2 C202.2 C203.2 C204.2 C205.2 C206.2 C207.2 C208.2 C209.2 C210.2 C211.2 C212.2 C213.2 C214.2 C215.2 C216.2 C217.2 C218.2 C219.2 C220.2 C221.2 C222.2 C401.2 C402.2 C403.2 C404.2 C405.2 C501.2 C502.2 C503.2 C504.2 C505.2 C506.2 C507.2 C508.2 C509.2 C801.2 C802.2 C803.2 C804.2 C805.2 C806.2 C807.2 C808.2 C809.2 D601.1(K) J801.11 J801.12 J801.13 J801.14 J801.15 J801.16 J801.17 J801.18 J801.28 J801.30 J801.35 J801.36 J801.45 J801.46 J801.52 J801.55 J801.62 J801.65 J801.71 J801.72 J802.1 J802.2 J802.7 J802.8 J802.13 J802.14 J802.19 J802.20 J802.25 J802.26 J802.31 J802.32 J802.37 J802.38 J802.43 J802.44 J802.48 J802.49 J802.54 J802.55 J802.60 J802.65 J802.66 J802.70 J802.71 J802.76 J802.79 J803.9 J803.10 J803.19 J803.20 J803.29 J803.30 J803.39 J803.40 J803.49 J803.50 J803.57 J803.60 J803.67 J803.68 J803.75 J803.76 J803.81 J803.82 J803.83 J803.84 J803.85 J803.86 J803.87 J803.88 R201.2 R204.2 R207.1 R208.1 R403.2 R415.2 R416.2 R417.2 R418.2 R609.2 R610.2 R611.2 R612.2 R614.2 TP615.1 TP617.1 TP801.1 TP802.1 TP803.1 TP804.1 U101.A1(VSS56) U101.A21(VSS1) U101.AA1(VSS54) U101.AA21(VSS55) U101.C2(VSS2) U101.C4(VSS3) U101.C6(VSS4) U101.C8(VSS5) U101.C10(VSS6) U101.C12(VSS7) U101.C14(VSS8) U101.C16(VSS9) U101.C18(VSS10) U101.E3(VSS11) U101.E19(VSS12) U101.G3(VSS13) U101.G19(VSS14) U101.H8(VSS15) U101.H10(VSS16) U101.H12(VSS17) U101.H14(VSS18) U101.J3(VSS19) U101.J5(VSS20) U101.J8(VSS21) U101.J14(VSS22) U101.J19(VSS23) U101.K11(VSS24) U101.L1(VSS25) U101.L3(VSS26) U101.L5(VSS27) U101.L8(VSS28) U101.L14(VSS29) U101.L19(VSS30) U101.M11(VSS31) U101.N3(VSS32) U101.N5(VSS33) U101.N8(VSS34) U101.N14(VSS35) U101.N19(VSS36) U101.P8(VSS37) U101.P10(VSS38) U101.P12(VSS39) U101.P14(VSS40) U101.R3(VSS41) U101.R19(VSS42) U101.T1(VSS43) U101.U3(VSS44) U101.U19(VSS45) U101.W4(VSS46) U101.W6(VSS47) U101.W10(VSS49) U101.W12(VSS50) U101.W14(VSS51) U101.W16(VSS52) U101.W18(VSS53) U201.A3(VSS) U201.A10(VSS) U201.AB3(VSS) U201.AB5(VSS) U201.AB8(VSS) U201.AB10(VSS) U201.C1(VSS) U201.C5(VSS) U201.C8(VSS) U201.C12(VSS) U201.D2(VSS) U201.D4(VSS) U201.D9(VSS) U201.D11(VSS) U201.E1(VSS) U201.E5(VSS) U201.E8(VSS) U201.E12(VSS) U201.G1(VSS) U201.G3(VSS) U201.G5(VSS) U201.G8(VSS) U201.G10(VSS) U201.G12(VSS) U201.J1(VSS) U201.J3(VSS) U201.J10(VSS) U201.J12(VSS) U201.K2(VSS) U201.K4(VSS) U201.K9(VSS) U201.K11(VSS) U201.N2(VSS) U201.N4(VSS) U201.N9(VSS) U201.N11(VSS) U201.P1(VSS) U201.P3(VSS) U201.P10(VSS) U201.P12(VSS) U201.T1(VSS) U201.T3(VSS) U201.T5(VSS) U201.T8(VSS) U201.T10(VSS) U201.T12(VSS) U201.V1(VSS) U201.V5(VSS) U201.V8(VSS) U201.V12(VSS) U201.W2(VSS) U201.W4(VSS) U201.W9(VSS) U201.W11(VSS) U201.Y1(VSS) U201.Y5(VSS) U201.Y8(VSS) U201.Y12(VSS) U501.A6(VSS1) U501.C4(VSSQ1) U501.E7(VSS2) U501.G5(VSS3) U501.H10(VSS4) U501.J5(VSS5) U501.K8(VSS6) U501.N2(VSSQ2) U501.N5(VSSQ3) U501.P4(VSSQ4) U501.P6(VSSQ5) Y401.2(GND1) Y401.4(GND2) ; also on sheet 8 10 12
VDD2_DDR: C136.1 C137.1 C138.1 C139.1 C140.1 C141.1 C156.1 R109.1 U101.L7(VDD2_DDR_2) U101.N6(VDD2_DDR_3) U101.N7(VDD2_DDR_4) U101.R6(VDD2_DDR_5) U101.T6(VDD2_DDR_1) ; also on sheet 10
VDD_1V8: C504.1 C505.1 C506.1 C507.1 C805.1 J801.19 J801.20 J801.21 J801.22 J801.23 J801.24 J801.25 J801.26 L102.1 R106.2 R202.1 R501.1 R502.1 U501.C6(VCCQ1) U501.M4(VCCQ2) U501.N4(VCCQ3) U501.P3(VCCQ4) U501.P5(VCCQ5) ; also on sheet 10 12
VDD_3V3: C501.1 C502.1 C503.1 C803.1 J803.91 J803.92 J803.93 J803.94 J803.95 J803.96 J803.97 J803.98 J803.99 J803.100 R105.1 R107.2 R605.1 U501.E6(VCC1) U501.F5(VCC2) U501.J10(VCC3) U501.K9(VCC4) ; also on sheet 10 12
VDD_ANA_0P8: C130.1 C131.1 C132.1 C134.1 C135.1 R103.2 U101.F10(VDD_USB_0P8) U101.G8(VDD_MIPI_0P8) U101.J15(VDD_ANA_0P8_1) U101.J16(VDD_ANA_0P8_2) U101.R14(VDD_ANA_0P8_3) ; also on sheet 10
VDD_ANA_0V8: R103.1 ; also on sheet 10 12
VDD_ANA_1P8: C142.1 C143.1 C144.1 C145.1 C146.1 C147.1 C148.1 C149.1 R104.2 U101.E8(VDD_USB_1P8) U101.F6(VDD_LVDS_1P8) U101.F8(VDD_MIPI_1P8) U101.F16(VDD_ANA0_1P8_1) U101.G16(VDD_ANA0_1P8_2) U101.L15(VDD_ANAVDET_1P8) U101.R8(VDD_ANA1_1P8) ; also on sheet 10
VDD_ANA_1V8: L102.2 R104.1 R111.2 ; also on sheet 10
VDD_SNVS_0V8: C102.1 U101.G14(VDD_BBSM_0P8_CAP)
VDD_SOC: C106.1 C107.1 C108.1 C109.1 C110.1 C111.1 C114.1 C124.1 R102.2 U101.J9(VDD_SOC1) U101.J10(VDD_SOC2) U101.J11(VDD_SOC3) U101.J12(VDD_SOC4) U101.J13(VDD_SOC5) U101.K9(VDD_SOC6) U101.K10(VDD_SOC7) U101.K12(VDD_SOC8) U101.K13(VDD_SOC9) U101.M9(VDD_SOC10) U101.M10(VDD_SOC11) U101.M12(VDD_SOC12) U101.M13(VDD_SOC13) U101.N9(VDD_SOC14) U101.N10(VDD_SOC15) U101.N11(VDD_SOC16) U101.N12(VDD_SOC17) U101.N13(VDD_SOC18) ; also on sheet 10
VDD_SOC_0V85: R102.1 ; also on sheet 10 12
VDD_USB_3P3: C155.1 R105.2 U101.G10(VDD_USB_3P3) ; also on sheet 10
VDDQ_DDR: C151.1 C152.1 C153.1 C154.1 R110.1 U101.G6(VDDQ_DDR_1) U101.J6(VDDQ_DDR_2) U101.J7(VDDQ_DDR_3) U101.L6(VDDQ_DDR_4) ; also on sheet 10
ADC_IN0: J802.72 TP413.1 U101.B19(ADC_IN0)
ADC_IN1: J802.74 TP414.1 U101.A20(ADC_IN1)
ADC_IN2: J802.78 TP415.1 U101.B20(ADC_IN2)
ADC_IN3: J802.80 TP416.1 U101.B21(ADC_IN3)
BB_VSYS_5V: C801.1 C802.1 J801.1 J801.2 J801.3 J801.4 J801.5 J801.6 J801.7 J801.8 J801.9 J801.10 R802.2 ; also on sheet 10
CLKIN1: J802.67 R415.1 TP418.1 U101.B17(CLKIN1)
CLKIN2: J802.69 R416.1 TP419.1 U101.A18(CLKIN2)
CLKO01: J801.79 U101.AA2(CCM_CLKO1)
CLKO02: J801.77 U101.Y3(CCM_CLKO2)
CLKO03: J801.75 U101.U4(CCM_CLKO3)
CLKO04: J801.73 U101.V4(CCM_CLKO4)
CSI_CLK_N: J802.47 ; also on sheet 8
CSI_CLK_P: J802.45 ; also on sheet 8
CSI_D0_N: J802.41 ; also on sheet 8
CSI_D0_P: J802.39 ; also on sheet 8
CSI_D1_N: J802.35 ; also on sheet 8
CSI_D1_P: J802.33 ; also on sheet 8
DRAM_CA0_A: U101.H2(DRAM_CA0_A) U201.H2(CA0_A)
DRAM_CA1_A: U101.G1(DRAM_CA1_A) U201.J2(CA1_A)
DRAM_CA2_A: U101.F2(DRAM_CA2_A) U201.H9(CA2_A)
DRAM_CA3_A: U101.E1(DRAM_CA3_A) U201.H10(CA3_A)
DRAM_CA4_A: U101.E2(DRAM_CA4_A) U201.H11(CA4_A)
DRAM_CA5_A: U101.D1(DRAM_CA5_A) U201.J11(CA5_A)
DRAM_CK_C_A: R205.2 U101.G5(DRAM_CK_C_A) U201.J9(CK_c_A)
DRAM_CK_T_A: R205.1 U101.G4(DRAM_CK_T_A) U201.J8(CK_t_A)
DRAM_CKE0_A: R207.2 U101.H1(DRAM_CKE0_A) U201.J4(CKE0_A)
DRAM_CKE1_A: R208.2 U101.J4(DRAM_CKE1_A) U201.J5(CKE1_A)
DRAM_DATA0_A: TP206.1 U101.N1(DRAM_DQ00_A) U201.F4(DQ4_A)
DRAM_DATA1_A: TP209.1 U101.N2(DRAM_DQ01_A) U201.E4(DQ5_A)
DRAM_DATA2_A: U101.M1(DRAM_DQ02_A) U201.C4(DQ6_A)
DRAM_DATA3_A: TP205.1 U101.M2(DRAM_DQ03_A) U201.B4(DQ7_A)
DRAM_DATA4_A: TP207.1 U101.K1(DRAM_DQ04_A) U201.B2(DQ0_A)
DRAM_DATA5_A: TP208.1 U101.K2(DRAM_DQ05_A) U201.C2(DQ1_A)
DRAM_DATA6_A: U101.J1(DRAM_DQ06_A) U201.E2(DQ2_A)
DRAM_DATA7_A: TP204.1 U101.J2(DRAM_DQ07_A) U201.F2(DQ3_A)
DRAM_DATA8_A: U101.V1(DRAM_DQ08_A) U201.E11(DQ10_A)
DRAM_DATA9_A: TP216.1 U101.V2(DRAM_DQ09_A) U201.F11(DQ11_A)
DRAM_DATA10_A: TP215.1 U101.U2(DRAM_DQ10_A) U201.C11(DQ9_A)
DRAM_DATA11_A: TP214.1 U101.U1(DRAM_DQ11_A) U201.B11(DQ8_A)
DRAM_DATA12_A: U101.R1(DRAM_DQ12_A) U201.C9(DQ14_A)
DRAM_DATA13_A: TP213.1 U101.R2(DRAM_DQ13_A) U201.B9(DQ15_A)
DRAM_DATA14_A: TP211.1 U101.P2(DRAM_DQ14_A) U201.E9(DQ13_A)
DRAM_DATA15_A: TP212.1 U101.P1(DRAM_DQ15_A) U201.F9(DQ12_A)
DRAM_DMI0_A: TP201.1 U101.L2(DRAM_DMI0_A) U201.C3(DMI0_A)
DRAM_DMI1_A: TP210.1 U101.T2(DRAM_DMI1_A) U201.C10(DMI1_A)
DRAM_nCS0_A: U101.F1(DRAM_CS0_A) U201.H4(CS0_A)
DRAM_nCS1_A: U101.G2(DRAM_CS1_A) U201.H3(CS1_A)
DRAM_nRESET: R201.1 U101.D2(DRAM_RESET_N) U201.T11(RESET_N)
DRAM_SDQS0_C_A: U101.L4(DRAM_DQS0_C_A) U201.E3(DQS0_c_A)
DRAM_SDQS0_T_A: U101.N4(DRAM_DQS0_T_A) U201.D3(DQS0_t_A)
DRAM_SDQS1_C_A: U101.R5(DRAM_DQS1_C_A) U201.E10(DQS1_c_A)
DRAM_SDQS1_T_A: U101.R4(DRAM_DQS1_T_A) U201.D10(DQS1_t_A)
DRAM_ZN: R204.1 U101.E4(DRAM_ZQ)
DRAM_ZQ0: R209.2 U201.A5(ZQ0)
DSI_CLK_N: J802.3 ; also on sheet 8
DSI_CLK_P: J802.5 ; also on sheet 8
DSI_D0_N: J802.9 ; also on sheet 8
DSI_D0_P: J802.11 ; also on sheet 8
DSI_D1_N: J802.15 ; also on sheet 8
DSI_D1_P: J802.17 ; also on sheet 8
DSI_D2_N: J802.21 ; also on sheet 8
DSI_D2_P: J802.23 ; also on sheet 8
DSI_D3_N: J802.27 ; also on sheet 8
DSI_D3_P: J802.29 ; also on sheet 8
eMMC_VDDIM: C508.1 C509.1 U501.C2(VDDI)
ENET1_MDC: J801.37 ; also on sheet 8
ENET1_MDIO: J801.39 ; also on sheet 8
ENET1_RD0: J801.49 ; also on sheet 8
ENET1_RD1: J801.47 ; also on sheet 8
ENET1_RD2: J801.43 ; also on sheet 8
ENET1_RD3: J801.41 ; also on sheet 8
ENET1_RX_CTL: J801.51 ; also on sheet 8
ENET1_RXC: J801.53 ; also on sheet 8
ENET1_TD0: J801.44 ; also on sheet 8
ENET1_TD1: J801.42 ; also on sheet 8
ENET1_TD2: J801.40 ; also on sheet 8
ENET1_TD3: J801.38 ; also on sheet 8
ENET1_TX_CTL: J801.48 ; also on sheet 8
ENET1_TXC: J801.50 ; also on sheet 8
ENET2_MDC: J801.54 ; also on sheet 8
ENET2_MDIO: J801.56 ; also on sheet 8
ENET2_RD0: J801.63 ; also on sheet 8
ENET2_RD1: J801.61 ; also on sheet 8
ENET2_RD2: J801.59 ; also on sheet 8
ENET2_RD3: J801.57 ; also on sheet 8
ENET2_RX_CTL: J801.67 ; also on sheet 8
ENET2_RXC: J801.69 ; also on sheet 8
ENET2_TD0: J801.66 ; also on sheet 8
ENET2_TD1: J801.64 ; also on sheet 8
ENET2_TD2: J801.60 ; also on sheet 8
ENET2_TD3: J801.58 ; also on sheet 8
ENET2_TX_CTL: J801.68 ; also on sheet 8
ENET2_TXC: J801.70 ; also on sheet 8
GPIO_IO00: J803.22 ; also on sheet 8
GPIO_IO01: J803.24 ; also on sheet 8
GPIO_IO02: J803.28 ; also on sheet 8
GPIO_IO03: J803.26 ; also on sheet 8
GPIO_IO04: J803.23 ; also on sheet 8
GPIO_IO05: J803.21 ; also on sheet 8
GPIO_IO06: J803.27 ; also on sheet 8
GPIO_IO07: J803.25 ; also on sheet 8
GPIO_IO08: J803.33 ; also on sheet 8
GPIO_IO09: J803.31 ; also on sheet 8
GPIO_IO10: J803.34 ; also on sheet 8
GPIO_IO11: J803.32 ; also on sheet 8
GPIO_IO12: J803.37 ; also on sheet 8
GPIO_IO13: J803.35 ; also on sheet 8
GPIO_IO14: J803.42 ; also on sheet 8
GPIO_IO15: J803.41 ; also on sheet 8
GPIO_IO16: J803.43 ; also on sheet 8
GPIO_IO17: J803.44 ; also on sheet 8
GPIO_IO18: J803.36 ; also on sheet 8
GPIO_IO19: J803.38 ; also on sheet 8
GPIO_IO20: J803.48 ; also on sheet 8
GPIO_IO21: J803.46 ; also on sheet 8
GPIO_IO22: J803.45 ; also on sheet 8
GPIO_IO23: J803.52 ; also on sheet 8
GPIO_IO24: J803.47 ; also on sheet 8
GPIO_IO25: J803.51 ; also on sheet 8
GPIO_IO26: J803.53 ; also on sheet 8
GPIO_IO27: J803.54 ; also on sheet 8
GPIO_IO28: J803.56 ; also on sheet 8
GPIO_IO29: J803.58 ; also on sheet 8
I2C1_SCL: J803.4 ; also on sheet 8 12
I2C1_SDA: J803.2 ; also on sheet 8 12
I2C2_SCL: J803.8 ; also on sheet 8 12
I2C2_SDA: J803.6 ; also on sheet 8 12
JTAG_TCK: J801.76 R403.1 TP404.1 U101.Y1(DAP_TCLK_SWCLK)
JTAG_TDI: J801.80 TP402.1 U101.W1(DAP_TDI)
JTAG_TDO: J801.74 TP405.1 U101.Y2(DAP_TDO_TRACESWO)
JTAG_TMS: J801.78 TP403.1 U101.W2(DAP_TMS_SWDIO)
LPD4/x_VDD1: C201.1 C202.1 C203.1 C204.1 C205.1 C209.1 R202.2 U201.F1(VDD1) U201.F12(VDD1) U201.G4(VDD1) U201.G9(VDD1) U201.T4(VDD1) U201.T9(VDD1) U201.U1(VDD1) U201.U12(VDD1) ; also on sheet 10
LPD4/x_VDD2: C206.1 C207.1 C208.1 C210.1 C211.1 C212.1 C213.1 C214.1 R203.2 R210.1 U201.A4(VDD2) U201.A9(VDD2) U201.AB4(VDD2) U201.AB9(VDD2) U201.F5(VDD2) U201.F8(VDD2) U201.H1(VDD2) U201.H5(VDD2) U201.H8(VDD2) U201.H12(VDD2) U201.K1(VDD2) U201.K3(VDD2) U201.K10(VDD2) U201.K12(VDD2) U201.N1(VDD2) U201.N3(VDD2) U201.N10(VDD2) U201.N12(VDD2) U201.R1(VDD2) U201.R5(VDD2) U201.R8(VDD2) U201.R12(VDD2) U201.U5(VDD2) U201.U8(VDD2) ; also on sheet 10
LPD4/x_VDD2_1V1: R109.2 R203.1 ; also on sheet 10 12
LPD4/x_VDDQ: C215.1 C216.1 C217.1 C218.1 C219.1 C220.1 C221.1 C222.1 R206.2 R209.1 R211.1 U201.AA3(VDDQ) U201.AA5(VDDQ) U201.AA8(VDDQ) U201.AA10(VDDQ) U201.B3(VDDQ) U201.B5(VDDQ) U201.B8(VDDQ) U201.B10(VDDQ) U201.D1(VDDQ) U201.D5(VDDQ) U201.D8(VDDQ) U201.D12(VDDQ) U201.F3(VDDQ) U201.F10(VDDQ) U201.U3(VDDQ) U201.U10(VDDQ) U201.W1(VDDQ) U201.W5(VDDQ) U201.W8(VDDQ) U201.W12(VDDQ) ; also on sheet 10
LPD4/x_VDDQ_0V6: R110.2 R206.1 ; also on sheet 10 12
LVDS_CLK_N: J802.18 ; also on sheet 8
LVDS_CLK_P: J802.16 ; also on sheet 8
LVDS_TX0_N: J802.30 ; also on sheet 8
LVDS_TX0_P: J802.28 ; also on sheet 8
LVDS_TX1_N: J802.24 ; also on sheet 8
LVDS_TX1_P: J802.22 ; also on sheet 8
LVDS_TX2_N: J802.12 ; also on sheet 8
LVDS_TX2_P: J802.10 ; also on sheet 8
LVDS_TX3_N: J802.6 ; also on sheet 8
LVDS_TX3_P: J802.4 ; also on sheet 8
MX_POR_B: C405.1 R404.2 R406.2 TP408.1 U101.A16(POR_B)
NVCC_1P8: C116.1 C117.1 R106.1 U101.R10(NVCC_WAKEUP1) U101.R12(NVCC_WAKEUP2) U101.W8(NVCC_WAKEUP3) ; also on sheet 10
NVCC_3P3: R107.1 R112.2 R113.2 ; also on sheet 10
NVCC_AON: C119.1 C804.1 J803.90 R112.1 R601.1 R602.1 R603.1 R604.1 TP608.1 U101.L16(NVCC_AON) ; also on sheet 8
NVCC_BBSM_1P8: C101.1 R101.2 U101.G12(NVCC_BBSM_1P8) ; also on sheet 10
NVCC_BBSM_1V8: C809.1 J802.53 R101.1 R401.1 R404.1 R405.1 ; also on sheet 10 12
NVCC_GPIO: C118.1 C806.1 J803.89 R113.1 U101.N15(NVCC_GPIO1) U101.N16(NVCC_GPIO2)
NVCC_SD: R108.2 ; also on sheet 10 12
NVCC_SD2: C129.1 C808.1 J803.55 R108.1 U101.R16(NVCC_SD2) ; also on sheet 8 10
ODT_CA_A: R210.2 U201.G2(ODT_CA_A)
ONOFF: J802.75 R405.2 TP401.1 U101.A19(ONOFF)
PDM_CLK: J803.11 ; also on sheet 8
PDM_DATA0: J803.13 ; also on sheet 8
PDM_DATA1: J803.15 ; also on sheet 8
PMIC_32K_OUT: J801.34 R411.1
PMIC_nINT: J801.32 ; also on sheet 12
PMIC_ON_REQ: J802.63 R401.2 R418.1 TP407.1 U101.A17(PMIC_ON_REQ) ; also on sheet 12
PMIC_SCLH: J801.31 ; also on sheet 12
PMIC_SCLL: J801.27 ; also on sheet 12
PMIC_SDAH: J801.33 ; also on sheet 12
PMIC_SDAL: J801.29 ; also on sheet 12
PMIC_STBY_REQ: J802.73 R417.1 TP409.1 U101.B18(PMIC_STBY_REQ)
POR_B: J802.57 R406.1 ; also on sheet 10 12
SAI1_RXD0: J803.18 ; also on sheet 8
SAI1_TXC: J803.14 ; also on sheet 8
SAI1_TXD0: J803.16 R604.2 R612.1 TP604.1 ; also on sheet 8
SAI1_TXFS: J803.12 R603.2 R611.1 TP603.1 ; also on sheet 8
SD1_CLK: TP503.1 U501.M6(CLK) ; also on sheet 8
SD1_CMD: R502.2 TP502.1 U501.M5(CMD) ; also on sheet 8
SD1_DATA0: R501.2 TP501.1 U501.A3(DAT0) ; also on sheet 8
SD1_DATA1: U501.A4(DAT1) ; also on sheet 8
SD1_DATA2: U501.A5(DAT2) ; also on sheet 8
SD1_DATA3: U501.B2(DAT3) ; also on sheet 8
SD1_DATA4: U501.B3(DAT4) ; also on sheet 8
SD1_DATA5: U501.B4(DAT5) ; also on sheet 8
SD1_DATA6: U501.B5(DAT6) ; also on sheet 8
SD1_DATA7: U501.B6(DAT7) ; also on sheet 8
SD1_STROBE: TP505.1 U501.H5(RCLK) ; also on sheet 8
SD2_CLK: J803.65 ; also on sheet 8
SD2_CMD: J803.63 ; also on sheet 8
SD2_DATA0: J803.69 ; also on sheet 8
SD2_DATA1: J803.71 ; also on sheet 8
SD2_DATA2: J803.59 ; also on sheet 8
SD2_DATA3: J803.61 ; also on sheet 8
SD2_nCD: J803.73 ; also on sheet 8
SD3_CLK: J803.62 ; also on sheet 8
SD3_CMD: J803.64 ; also on sheet 8
SD3_DATA0: J803.66 ; also on sheet 8
SD3_DATA1: J803.70 ; also on sheet 8
SD3_DATA2: J803.72 ; also on sheet 8
SD3_DATA3: J803.74 ; also on sheet 8
SYS_nRST: J802.77 ; also on sheet 12
TAMPER0: J802.61 TP410.1 U101.B16(TAMPER0)
TAMPER1: J802.59 TP411.1 U101.F14(TAMPER1)
UART1_RXD: J803.3 TP612.1 ; also on sheet 8
UART1_TXD: J803.1 R601.2 R609.1 TP610.1 ; also on sheet 8
UART2_RXD: J803.7 TP616.1 ; also on sheet 8
UART2_TXD: J803.5 R602.2 R610.1 TP614.1 ; also on sheet 8
USB1_DN: J802.50 TP611.1 ; also on sheet 8
USB1_DP: J802.52 TP613.1 ; also on sheet 8
USB1_ID: J802.56 ; also on sheet 8
USB1_RXN: J802.34 ; also on sheet 8
USB1_RXP: J802.36 ; also on sheet 8
USB1_TXN: J802.40 ; also on sheet 8
USB1_TXP: J802.42 ; also on sheet 8
USB1_VBUS: R613.1 TP609.1
USB1_VBUS_3V3: J802.46 R613.2 R614.1 ; also on sheet 8
USB2_DN: J802.62 ; also on sheet 8
USB2_DP: J802.64 ; also on sheet 8
USB2_ID: J802.68 ; also on sheet 8
USB2_VBUS_3V3: J802.58 ; also on sheet 8
VLDO3_1V8: R111.1 ; also on sheet 12
VSD2_3V3: C807.1 J803.77 J803.78 J803.79 J803.80 R801.2 ; also on sheet 10
VSD_3V3: R801.1 ; also on sheet 10 12
VSYS_5V: R802.1 TP607.1 ; also on sheet 10 12
WDOG_B: J803.17 ; also on sheet 8
XTALI_24M: C403.1 R414.1 TP417.1 U101.D18(XTALI_24M) Y401.1
XTALI_32K: R411.2 R412.1 TP412.1 U101.E16(RTC_XTALI)
XTALO_24M: C404.1 R414.2 U101.E18(XTALO_24M) Y401.3
XTALO_32K: C402.1 QZ401.1 R413.2 U101.D16(RTC_XTALO)
N113524078: C401.1 QZ401.2 R412.2 R413.1
N114616846: D601.2(A) R605.2
N116675602: TP202.1 U101.D4(DRAM_MTEST1)
N116676339: TP504.1 U501.K5(~{RST})
N116698763: R211.2 U201.A8(ZQ1)
N116700633: J802.51 TP805.1

Not connected (* = marked no-connect by the designer): J801 M1* M2* M3* M4*; J802 M1* M2* M3* M4*; J803 S1* S2* S3* S4*; U201 A1(DNU)* A2(DNU)* A11(DNU)* A12(DNU)* AA1(DNU)* AA2(DQ0_B)* AA4(DQ7_B)* AA9(DQ15_B)* AA11(DQ8_B)* AA12(DNU)* AB1(DNU)* AB2(DNU)* AB11(DNU)* AB12(DNU)* B1(DNU)* B12(DNU)* G11(NC)* K5(NC)* K8(NC)* N5(NC)* N8(NC)* P2(CA1_B)* P4(CKE0_B)* P5(CKE1_B)* P8(CK_t_B)* P9(CK_c_B)* P11(CA5_B)* R2(CA0_B)* R3(CS1_B)* R4(CS0_B)* R9(CA2_B)* R10(CA3_B)* R11(CA4_B)* T2(ODT_CA_B)* U2(DQ3_B)* U4(DQ4_B)* U9(DQ12_B)* U11(DQ11_B)* V2(DQ2_B)* V3(DQS0_c_B)* V4(DQ5_B)* V9(DQ13_B)* V10(DQS1_c_B)* V11(DQ10_B)* W3(DQS0_t_B)* W10(DQS1_t_B)* Y2(DQ1_B)* Y3(DMI0_B)* Y4(DQ6_B)* Y9(DQ14_B)* Y10(DMI1_B)* Y11(DQ9_B)*; U501 A1(NC)* A2(NC)* A7(NC)* A8(NC)* A9(NC)* A10(NC)* A11(NC)* A12(NC)* A13(NC)* A14(NC)* B1(NC)* B7(NC)* B8(NC)* B9(NC)* B10(NC)* B11(NC)* B12(NC)* B13(NC)* B14(NC)* C1(NC)* C3(NC)* C5(NC)* C7(NC)* C8(NC)* C9(NC)* C10(NC)* C11(NC)* C12(NC)* C13(NC)* C14(NC)* D1(NC)* D2(NC)* D3(NC)* D4(NC)* D12(NC)* D13(NC)* D14(NC)* E1(NC)* E2(NC)* E3(NC)* E5(NC)* E8(NC)* E9(VSF1)* E10(VSF2)* E12(NC)* E13(NC)* E14(NC)* F1(NC)* F2(NC)* F3(NC)* F10(VSF3)* F12(NC)* F13(NC)* F14(NC)* G1(NC)* G2(NC)* G3(NC)* G10(NC)* G12(NC)* G13(NC)* G14(NC)* H1(NC)* H2(NC)* H3(NC)* H12(NC)* H13(NC)* H14(NC)* J1(NC)* J2(NC)* J3(NC)* J12(NC)* J13(NC)* J14(NC)* K1(NC)* K2(NC)* K3(NC)* K6(NC)* K7(NC)* K10(VSF4)* K12(NC)* K13(NC)* K14(NC)* L1(NC)* L2(NC)* L3(NC)* L12(NC)* L13(NC)* L14(NC)* M1(NC)* M2(NC)* M3(NC)* M7(NC)* M8(NC)* M9(NC)* M10(NC)* M11(NC)* M12(NC)* M13(NC)* M14(NC)* N1(NC)* N3(NC)* N6(NC)* N7(NC)* N8(NC)* N9(NC)* N10(NC)* N11(NC)* N12(NC)* N13(NC)* N14(NC)* P1(NC)* P2(NC)* P7(NC)* P8(NC)* P9(NC)* P10(NC)* P11(NC)* P12(NC)* P13(NC)* P14(NC)*

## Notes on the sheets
sheet 1
- i.MX93 MISC
- JTAG/SWD
- # System On/Off Button
sheet 2
- LPDDR4
- # VDD1: 1.8V /400mA
- # VDD2 : 1.1V / 600mA
- Note 03_A:-
  We are using the LPDDR4 so
   VDDQ of LPDDR4 = 1.1V
  LPD4/x_VDDQ_0V6 ===LPD4/x_VDD2_1V1
  See Page no 10 for more details
- # VDDQ: (0.6V/1.1V) / 360mA
- LPDDR4: 2GB (x16)
- Z:85 OHM
- Z:85 OHM
- Z:85 OHM
- # ZQ1 is reserved for 2CS LPDDR4/x
- Note 03_B:-
  We can scale up to dual channel
   but in current design we are using
  the single channel.
  MPN: MT53E1G16D1ZW-046 AAT:C
sheet 3
- FLASH: eMMC <5.1>
- Note 04:
  Layout :-All the CAPs in this page need to be put on the bottom of BGA,
  and close the PINs as short as possible.
sheet 4
- REV
- Revision Notes
- Designer
- Approver
- Date
- i.MX 93 SOM BOARD
- ROHIT
- CHETAN SINGH
- 12-02-2024
- A03
- INITIAL RELEASE
- A04
- TI COMMENTS IMPLEMENTATION
- SHIVAM
- CHETAN SINGH
- 29-02-2024
- A1
- PROTO RELEASE
- ROHIT/SHIVAM
- CHETAN SINGH
- 27-03-2024
- i.MX93 SOM Board with TPS6521905 TI PMIC
- Contents
- Page No
- Sheet Name
- 01
- COVER PAGE
- 02
- i.MX93  BLOCK DIAGRAM
- 03
- POWER ARCHITECTURE
- 04
- i.MX93 POWER
- 05
- LPDDR4
- 06
- i.MX93 IO/PHY
- 07
- i.MX93 MISC
- 08
- eMMC
- 09
- BOOT CONFIG
- 10
- PMIC TI AND EXT REGULATOR
- 11
- HDR CONNECTORS
- 12
- POWER MEASUREMENT
- 501-1-03450
- 701-1-04331
sheet 5
- B2B CN for CPU SOM
- HDR
- HDR
- HDR
- #MIPI DSI/CSI Z:100 OHM
- #LVDS Z:100 OHM
- NVCC_SD2 <1.8V/3.3V>
- 1.8V RAIL
- RFU
- #USB3.0 Z:100 OHM
- #USB2.0 Z:90 OHM
- 3.3V PWR RAIL
- 3.3V RAIL
- #USB2.0 Z:90 OHM
- GND TP
- SCREW HOLE
sheet 6
- i.MX93 PWR
- Note 1:- Placed  all the green highlight RES (in this page 4) while no PWR MEAS required
- Note 01:
  Layout :-All the CAPs in this page need to be put on the bottom of BGA,
  and close the PINs as short as possible.
- # NVCC_BBSM_1P8: 1.8V / 2mA
- Imax = N x C x V x (0.5 x F)
- # VDD_SOC: (0.65V-0.9V)
- # VDD_xxx_0P8: 0.8V / 186mA
- # VDD_xxx_1P8: 1.8V / 388.2mA
- # ADC ENOB can be lower than shown if excessive noise is present
  on VDD_ANAx_1P8, including ripple from DC/DC converter
- # VDD_USB_3V3: 3.3V / 25.2mA
- Note 02:-for VDDQ of LPDDR4
  we are giving 1.1V so here
  LPD4/x_VDDQ_0V6 ===LPD4/x_VDD2_1V1
  See Page no 10 for more details
sheet 7
- Boot Mode and CFG Switch
- i.MX93 BOOT MODE
- BOOT_MODE[3:0]
- BOOT CORE
- BOOT DEVICE
- 0010
- Cortex-A55
- USDHC1 8-bit eMMC 5.1
- Note 05:
  For more details: Please refer to the Page No: 85  for Boot Mode Configuration
  in i.MX93 datasheet
- # BOOT_MODE1 PU on SOM , designed
  for eMMC boot by default on SOM w/o BB
  required.
- BOOT CFG
- #BOOT_MODE0
- #BOOT_MODE1
- #BOOT_MODE2
- #BOOT_MODE3
- #SoC PU/PD:
        27K-32K-38K <MIN-TYP-MAX>
- #A53 DBG
- #M33 DBG
- # USB Serial Download
- LED GREEN
- Manufacturing Test
